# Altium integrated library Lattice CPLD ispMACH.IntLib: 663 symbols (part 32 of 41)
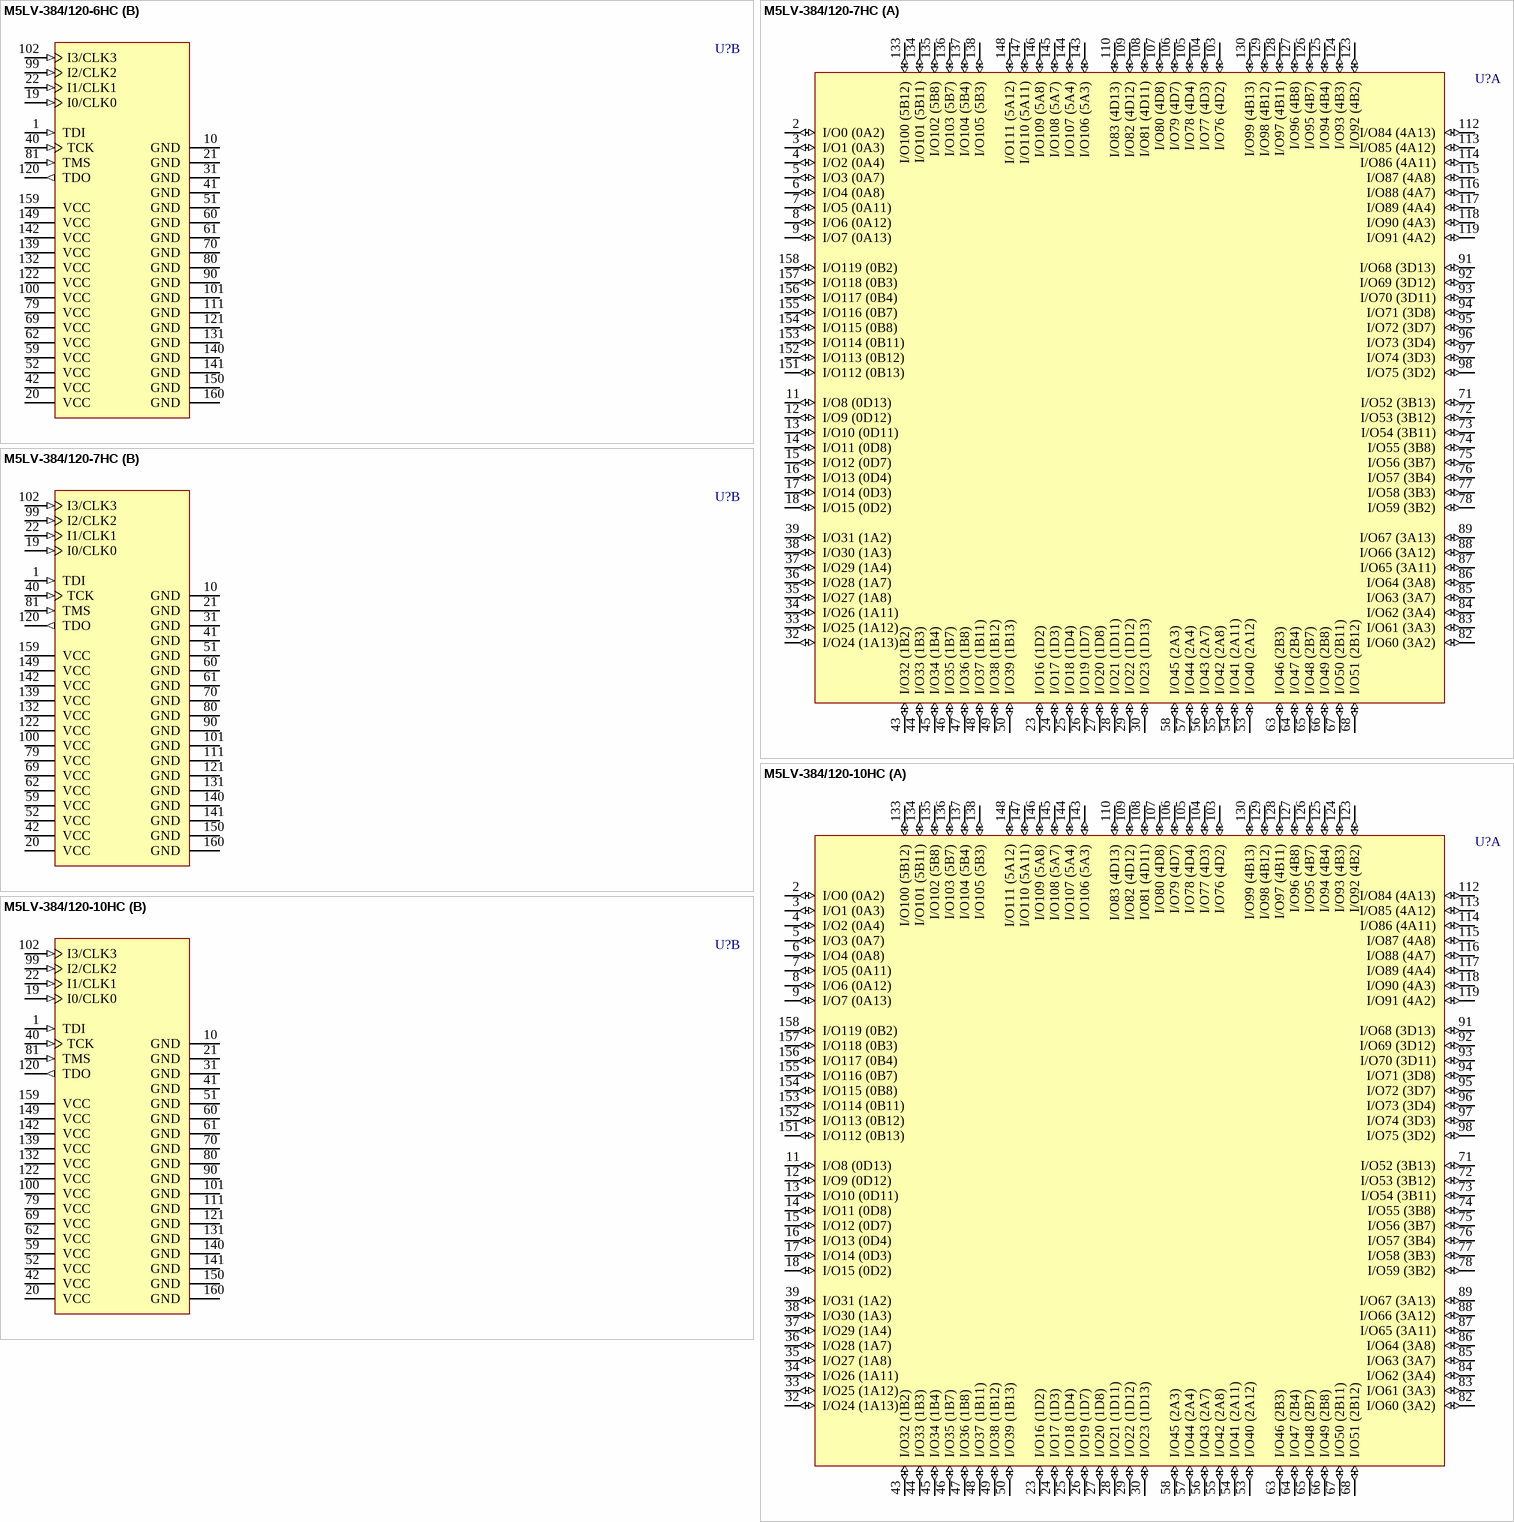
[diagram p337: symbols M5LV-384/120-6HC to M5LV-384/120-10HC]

## M5LV-384/120-7HC
designator U?
High-Density and High-I/O Complex PLD
footprint MQFP160_N (QFP, 160-Leads, Body 27.7 x 27.7mm, Pitch 0.65mm, IPC Medium Density)
footprint MQFP160_L (QFP, 160-Leads, Body 27.7 x 27.7mm, Pitch 0.65mm, IPC High Density)
footprint MQFP160_M (QFP, 160-Leads, Body 27.7 x 27.7mm, Pitch 0.65mm, IPC Low Density)
3D model M5LV-MQFP160 (160-Pin Quad Flat Pack 0.65 mm Pitch)
part A pins: 2 I/O0 (0A2) (io), 3 I/O1 (0A3) (io), 4 I/O2 (0A4) (io), 5 I/O3 (0A7) (io), 6 I/O4 (0A8) (io), 7 I/O5 (0A11) (io), 8 I/O6 (0A12) (io), 9 I/O7 (0A13) (io), 11 I/O8 (0D13) (io), 12 I/O9 (0D12) (io), 13 I/O10 (0D11) (io), 14 I/O11 (0D8) (io), 15 I/O12 (0D7) (io), 16 I/O13 (0D4) (io), 17 I/O14 (0D3) (io), 18 I/O15 (0D2) (io), 23 I/O16 (1D2) (io), 24 I/O17 (1D3) (io), 25 I/O18 (1D4) (io), 26 I/O19 (1D7) (io), 27 I/O20 (1D8) (io), 28 I/O21 (1D11) (io), 29 I/O22 (1D12) (io), 30 I/O23 (1D13) (io), 32 I/O24 (1A13) (io), 33 I/O25 (1A12) (io), 34 I/O26 (1A11) (io), 35 I/O27 (1A8) (io), 36 I/O28 (1A7) (io), 37 I/O29 (1A4) (io), 38 I/O30 (1A3) (io), 39 I/O31 (1A2) (io), 43 I/O32 (1B2) (io), 44 I/O33 (1B3) (io), 45 I/O34 (1B4) (io), 46 I/O35 (1B7) (io), 47 I/O36 (1B8) (io), 48 I/O37 (1B11) (io), 49 I/O38 (1B12) (io), 50 I/O39 (1B13) (io), 53 I/O40 (2A12) (io), 54 I/O41 (2A11) (io), 55 I/O42 (2A8) (io), 56 I/O43 (2A7) (io), 57 I/O44 (2A4) (io), 58 I/O45 (2A3) (io), 63 I/O46 (2B3) (io), 64 I/O47 (2B4) (io), 65 I/O48 (2B7) (io), 66 I/O49 (2B8) (io), 67 I/O50 (2B11) (io), 68 I/O51 (2B12) (io), 71 I/O52 (3B13) (io), 72 I/O53 (3B12) (io), 73 I/O54 (3B11) (io), 74 I/O55 (3B8) (io), 75 I/O56 (3B7) (io), 76 I/O57 (3B4) (io), 77 I/O58 (3B3) (io), 78 I/O59 (3B2) (io), 82 I/O60 (3A2) (io), 83 I/O61 (3A3) (io), 84 I/O62 (3A4) (io), 85 I/O63 (3A7) (io), 86 I/O64 (3A8) (io), 87 I/O65 (3A11) (io), 88 I/O66 (3A12) (io), 89 I/O67 (3A13) (io), 91 I/O68 (3D13) (io), 92 I/O69 (3D12) (io), 93 I/O70 (3D11) (io), 94 I/O71 (3D8) (io), 95 I/O72 (3D7) (io), 96 I/O73 (3D4) (io), 97 I/O74 (3D3) (io), 98 I/O75 (3D2) (io), 103 I/O76 (4D2) (io), 104 I/O77 (4D3) (io), 105 I/O78 (4D4) (io), 106 I/O79 (4D7) (io), 107 I/O80 (4D8) (io), 108 I/O81 (4D11) (io), 109 I/O82 (4D12) (io), 110 I/O83 (4D13) (io), 112 I/O84 (4A13) (io), 113 I/O85 (4A12) (io), 114 I/O86 (4A11) (io), 115 I/O87 (4A8) (io), 116 I/O88 (4A7) (io), 117 I/O89 (4A4) (io), 118 I/O90 (4A3) (io), 119 I/O91 (4A2) (io), 123 I/O92 (4B2) (io), 124 I/O93 (4B3) (io), 125 I/O94 (4B4) (io), 126 I/O95 (4B7) (io), 127 I/O96 (4B8) (io), 128 I/O97 (4B11) (io), 129 I/O98 (4B12) (io), 130 I/O99 (4B13) (io), 133 I/O100 (5B12) (io), 134 I/O101 (5B11) (io), 135 I/O102 (5B8) (io), 136 I/O103 (5B7) (io), 137 I/O104 (5B4) (io), 138 I/O105 (5B3) (io), 143 I/O106 (5A3) (io), 144 I/O107 (5A4) (io), 145 I/O108 (5A7) (io), 146 I/O109 (5A8) (io), 147 I/O110 (5A11) (io), 148 I/O111 (5A12) (io), 151 I/O112 (0B13) (io), 152 I/O113 (0B12) (io), 153 I/O114 (0B11) (io), 154 I/O115 (0B8) (io), 155 I/O116 (0B7) (io), 156 I/O117 (0B4) (io), 157 I/O118 (0B3) (io), 158 I/O119 (0B2) (io)
part B pins: 1 TDI (in), 10 GND (power), 19 I0/CLK0 (in), 20 VCC (power), 21 GND (power), 22 I1/CLK1 (in), 31 GND (power), 40 TCK (in), 41 GND (power), 42 VCC (power), 51 GND (power), 52 VCC (power), 59 VCC (power), 60 GND (power), 61 GND (power), 62 VCC (power), 69 VCC (power), 70 GND (power), 79 VCC (power), 80 GND (power), 81 TMS (in), 90 GND (power), 99 I2/CLK2 (in), 100 VCC (power), 101 GND (power), 102 I3/CLK3 (in), 111 GND (power), 120 TDO (out), 121 GND (power), 122 VCC (power), 131 GND (power), 132 VCC (power), 139 VCC (power), 140 GND (power), 141 GND (power), 142 VCC (power), 149 VCC (power), 150 GND (power), 159 VCC (power), 160 GND (power)

## M5LV-384/120-10HC
designator U?
High-Density and High-I/O Complex PLD
footprint MQFP160_N (QFP, 160-Leads, Body 27.7 x 27.7mm, Pitch 0.65mm, IPC Medium Density)
footprint MQFP160_L (QFP, 160-Leads, Body 27.7 x 27.7mm, Pitch 0.65mm, IPC High Density)
footprint MQFP160_M (QFP, 160-Leads, Body 27.7 x 27.7mm, Pitch 0.65mm, IPC Low Density)
3D model M5LV-MQFP160 (160-Pin Quad Flat Pack 0.65 mm Pitch)
part A pins: 2 I/O0 (0A2) (io), 3 I/O1 (0A3) (io), 4 I/O2 (0A4) (io), 5 I/O3 (0A7) (io), 6 I/O4 (0A8) (io), 7 I/O5 (0A11) (io), 8 I/O6 (0A12) (io), 9 I/O7 (0A13) (io), 11 I/O8 (0D13) (io), 12 I/O9 (0D12) (io), 13 I/O10 (0D11) (io), 14 I/O11 (0D8) (io), 15 I/O12 (0D7) (io), 16 I/O13 (0D4) (io), 17 I/O14 (0D3) (io), 18 I/O15 (0D2) (io), 23 I/O16 (1D2) (io), 24 I/O17 (1D3) (io), 25 I/O18 (1D4) (io), 26 I/O19 (1D7) (io), 27 I/O20 (1D8) (io), 28 I/O21 (1D11) (io), 29 I/O22 (1D12) (io), 30 I/O23 (1D13) (io), 32 I/O24 (1A13) (io), 33 I/O25 (1A12) (io), 34 I/O26 (1A11) (io), 35 I/O27 (1A8) (io), 36 I/O28 (1A7) (io), 37 I/O29 (1A4) (io), 38 I/O30 (1A3) (io), 39 I/O31 (1A2) (io), 43 I/O32 (1B2) (io), 44 I/O33 (1B3) (io), 45 I/O34 (1B4) (io), 46 I/O35 (1B7) (io), 47 I/O36 (1B8) (io), 48 I/O37 (1B11) (io), 49 I/O38 (1B12) (io), 50 I/O39 (1B13) (io), 53 I/O40 (2A12) (io), 54 I/O41 (2A11) (io), 55 I/O42 (2A8) (io), 56 I/O43 (2A7) (io), 57 I/O44 (2A4) (io), 58 I/O45 (2A3) (io), 63 I/O46 (2B3) (io), 64 I/O47 (2B4) (io), 65 I/O48 (2B7) (io), 66 I/O49 (2B8) (io), 67 I/O50 (2B11) (io), 68 I/O51 (2B12) (io), 71 I/O52 (3B13) (io), 72 I/O53 (3B12) (io), 73 I/O54 (3B11) (io), 74 I/O55 (3B8) (io), 75 I/O56 (3B7) (io), 76 I/O57 (3B4) (io), 77 I/O58 (3B3) (io), 78 I/O59 (3B2) (io), 82 I/O60 (3A2) (io), 83 I/O61 (3A3) (io), 84 I/O62 (3A4) (io), 85 I/O63 (3A7) (io), 86 I/O64 (3A8) (io), 87 I/O65 (3A11) (io), 88 I/O66 (3A12) (io), 89 I/O67 (3A13) (io), 91 I/O68 (3D13) (io), 92 I/O69 (3D12) (io), 93 I/O70 (3D11) (io), 94 I/O71 (3D8) (io), 95 I/O72 (3D7) (io), 96 I/O73 (3D4) (io), 97 I/O74 (3D3) (io), 98 I/O75 (3D2) (io), 103 I/O76 (4D2) (io), 104 I/O77 (4D3) (io), 105 I/O78 (4D4) (io), 106 I/O79 (4D7) (io), 107 I/O80 (4D8) (io), 108 I/O81 (4D11) (io), 109 I/O82 (4D12) (io), 110 I/O83 (4D13) (io), 112 I/O84 (4A13) (io), 113 I/O85 (4A12) (io), 114 I/O86 (4A11) (io), 115 I/O87 (4A8) (io), 116 I/O88 (4A7) (io), 117 I/O89 (4A4) (io), 118 I/O90 (4A3) (io), 119 I/O91 (4A2) (io), 123 I/O92 (4B2) (io), 124 I/O93 (4B3) (io), 125 I/O94 (4B4) (io), 126 I/O95 (4B7) (io), 127 I/O96 (4B8) (io), 128 I/O97 (4B11) (io), 129 I/O98 (4B12) (io), 130 I/O99 (4B13) (io), 133 I/O100 (5B12) (io), 134 I/O101 (5B11) (io), 135 I/O102 (5B8) (io), 136 I/O103 (5B7) (io), 137 I/O104 (5B4) (io), 138 I/O105 (5B3) (io), 143 I/O106 (5A3) (io), 144 I/O107 (5A4) (io), 145 I/O108 (5A7) (io), 146 I/O109 (5A8) (io), 147 I/O110 (5A11) (io), 148 I/O111 (5A12) (io), 151 I/O112 (0B13) (io), 152 I/O113 (0B12) (io), 153 I/O114 (0B11) (io), 154 I/O115 (0B8) (io), 155 I/O116 (0B7) (io), 156 I/O117 (0B4) (io), 157 I/O118 (0B3) (io), 158 I/O119 (0B2) (io)
part B pins: 1 TDI (in), 10 GND (power), 19 I0/CLK0 (in), 20 VCC (power), 21 GND (power), 22 I1/CLK1 (in), 31 GND (power), 40 TCK (in), 41 GND (power), 42 VCC (power), 51 GND (power), 52 VCC (power), 59 VCC (power), 60 GND (power), 61 GND (power), 62 VCC (power), 69 VCC (power), 70 GND (power), 79 VCC (power), 80 GND (power), 81 TMS (in), 90 GND (power), 99 I2/CLK2 (in), 100 VCC (power), 101 GND (power), 102 I3/CLK3 (in), 111 GND (power), 120 TDO (out), 121 GND (power), 122 VCC (power), 131 GND (power), 132 VCC (power), 139 VCC (power), 140 GND (power), 141 GND (power), 142 VCC (power), 149 VCC (power), 150 GND (power), 159 VCC (power), 160 GND (power)

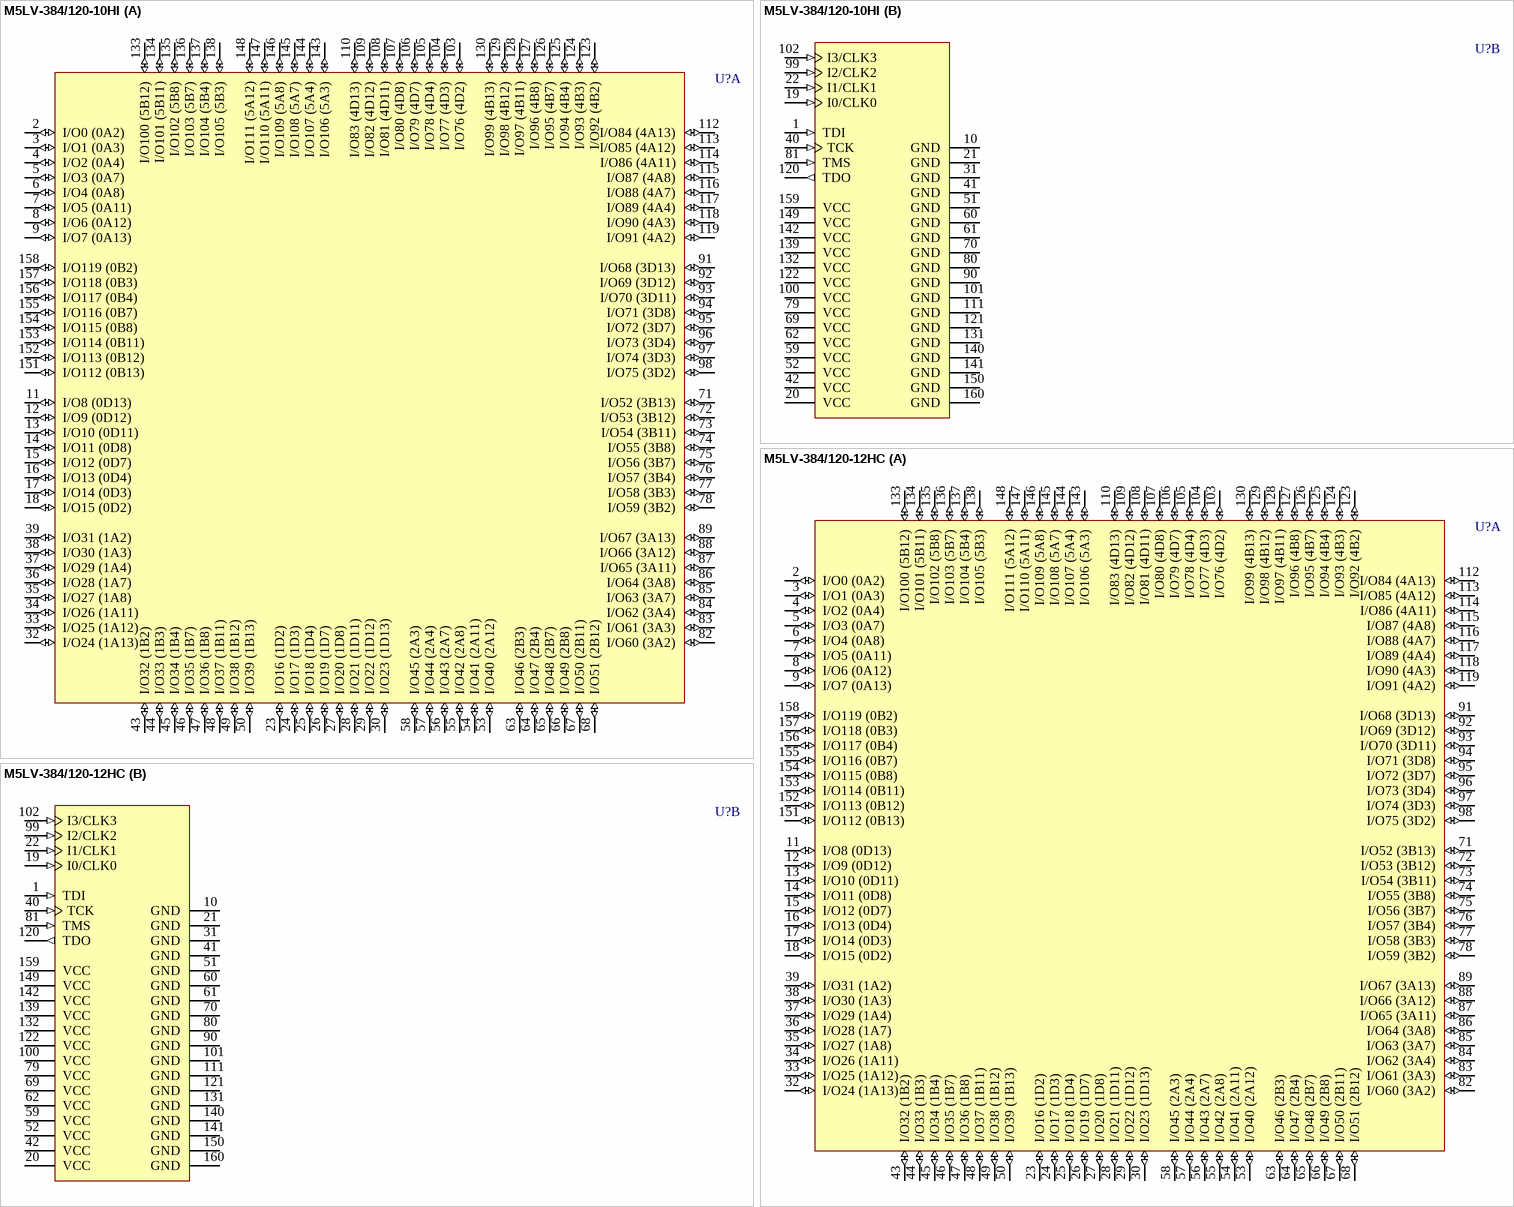
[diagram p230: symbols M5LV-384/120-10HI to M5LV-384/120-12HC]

## M5LV-384/120-10HI
designator U?
High-Density and High-I/O Complex PLD
footprint MQFP160_N (QFP, 160-Leads, Body 27.7 x 27.7mm, Pitch 0.65mm, IPC Medium Density)
footprint MQFP160_L (QFP, 160-Leads, Body 27.7 x 27.7mm, Pitch 0.65mm, IPC High Density)
footprint MQFP160_M (QFP, 160-Leads, Body 27.7 x 27.7mm, Pitch 0.65mm, IPC Low Density)
3D model M5LV-MQFP160 (160-Pin Quad Flat Pack 0.65 mm Pitch)
part A pins: 2 I/O0 (0A2) (io), 3 I/O1 (0A3) (io), 4 I/O2 (0A4) (io), 5 I/O3 (0A7) (io), 6 I/O4 (0A8) (io), 7 I/O5 (0A11) (io), 8 I/O6 (0A12) (io), 9 I/O7 (0A13) (io), 11 I/O8 (0D13) (io), 12 I/O9 (0D12) (io), 13 I/O10 (0D11) (io), 14 I/O11 (0D8) (io), 15 I/O12 (0D7) (io), 16 I/O13 (0D4) (io), 17 I/O14 (0D3) (io), 18 I/O15 (0D2) (io), 23 I/O16 (1D2) (io), 24 I/O17 (1D3) (io), 25 I/O18 (1D4) (io), 26 I/O19 (1D7) (io), 27 I/O20 (1D8) (io), 28 I/O21 (1D11) (io), 29 I/O22 (1D12) (io), 30 I/O23 (1D13) (io), 32 I/O24 (1A13) (io), 33 I/O25 (1A12) (io), 34 I/O26 (1A11) (io), 35 I/O27 (1A8) (io), 36 I/O28 (1A7) (io), 37 I/O29 (1A4) (io), 38 I/O30 (1A3) (io), 39 I/O31 (1A2) (io), 43 I/O32 (1B2) (io), 44 I/O33 (1B3) (io), 45 I/O34 (1B4) (io), 46 I/O35 (1B7) (io), 47 I/O36 (1B8) (io), 48 I/O37 (1B11) (io), 49 I/O38 (1B12) (io), 50 I/O39 (1B13) (io), 53 I/O40 (2A12) (io), 54 I/O41 (2A11) (io), 55 I/O42 (2A8) (io), 56 I/O43 (2A7) (io), 57 I/O44 (2A4) (io), 58 I/O45 (2A3) (io), 63 I/O46 (2B3) (io), 64 I/O47 (2B4) (io), 65 I/O48 (2B7) (io), 66 I/O49 (2B8) (io), 67 I/O50 (2B11) (io), 68 I/O51 (2B12) (io), 71 I/O52 (3B13) (io), 72 I/O53 (3B12) (io), 73 I/O54 (3B11) (io), 74 I/O55 (3B8) (io), 75 I/O56 (3B7) (io), 76 I/O57 (3B4) (io), 77 I/O58 (3B3) (io), 78 I/O59 (3B2) (io), 82 I/O60 (3A2) (io), 83 I/O61 (3A3) (io), 84 I/O62 (3A4) (io), 85 I/O63 (3A7) (io), 86 I/O64 (3A8) (io), 87 I/O65 (3A11) (io), 88 I/O66 (3A12) (io), 89 I/O67 (3A13) (io), 91 I/O68 (3D13) (io), 92 I/O69 (3D12) (io), 93 I/O70 (3D11) (io), 94 I/O71 (3D8) (io), 95 I/O72 (3D7) (io), 96 I/O73 (3D4) (io), 97 I/O74 (3D3) (io), 98 I/O75 (3D2) (io), 103 I/O76 (4D2) (io), 104 I/O77 (4D3) (io), 105 I/O78 (4D4) (io), 106 I/O79 (4D7) (io), 107 I/O80 (4D8) (io), 108 I/O81 (4D11) (io), 109 I/O82 (4D12) (io), 110 I/O83 (4D13) (io), 112 I/O84 (4A13) (io), 113 I/O85 (4A12) (io), 114 I/O86 (4A11) (io), 115 I/O87 (4A8) (io), 116 I/O88 (4A7) (io), 117 I/O89 (4A4) (io), 118 I/O90 (4A3) (io), 119 I/O91 (4A2) (io), 123 I/O92 (4B2) (io), 124 I/O93 (4B3) (io), 125 I/O94 (4B4) (io), 126 I/O95 (4B7) (io), 127 I/O96 (4B8) (io), 128 I/O97 (4B11) (io), 129 I/O98 (4B12) (io), 130 I/O99 (4B13) (io), 133 I/O100 (5B12) (io), 134 I/O101 (5B11) (io), 135 I/O102 (5B8) (io), 136 I/O103 (5B7) (io), 137 I/O104 (5B4) (io), 138 I/O105 (5B3) (io), 143 I/O106 (5A3) (io), 144 I/O107 (5A4) (io), 145 I/O108 (5A7) (io), 146 I/O109 (5A8) (io), 147 I/O110 (5A11) (io), 148 I/O111 (5A12) (io), 151 I/O112 (0B13) (io), 152 I/O113 (0B12) (io), 153 I/O114 (0B11) (io), 154 I/O115 (0B8) (io), 155 I/O116 (0B7) (io), 156 I/O117 (0B4) (io), 157 I/O118 (0B3) (io), 158 I/O119 (0B2) (io)
part B pins: 1 TDI (in), 10 GND (power), 19 I0/CLK0 (in), 20 VCC (power), 21 GND (power), 22 I1/CLK1 (in), 31 GND (power), 40 TCK (in), 41 GND (power), 42 VCC (power), 51 GND (power), 52 VCC (power), 59 VCC (power), 60 GND (power), 61 GND (power), 62 VCC (power), 69 VCC (power), 70 GND (power), 79 VCC (power), 80 GND (power), 81 TMS (in), 90 GND (power), 99 I2/CLK2 (in), 100 VCC (power), 101 GND (power), 102 I3/CLK3 (in), 111 GND (power), 120 TDO (out), 121 GND (power), 122 VCC (power), 131 GND (power), 132 VCC (power), 139 VCC (power), 140 GND (power), 141 GND (power), 142 VCC (power), 149 VCC (power), 150 GND (power), 159 VCC (power), 160 GND (power)

## M5LV-384/120-12HC
designator U?
High-Density and High-I/O Complex PLD
footprint MQFP160_N (QFP, 160-Leads, Body 27.7 x 27.7mm, Pitch 0.65mm, IPC Medium Density)
footprint MQFP160_L (QFP, 160-Leads, Body 27.7 x 27.7mm, Pitch 0.65mm, IPC High Density)
footprint MQFP160_M (QFP, 160-Leads, Body 27.7 x 27.7mm, Pitch 0.65mm, IPC Low Density)
3D model M5LV-MQFP160 (160-Pin Quad Flat Pack 0.65 mm Pitch)
part A pins: 2 I/O0 (0A2) (io), 3 I/O1 (0A3) (io), 4 I/O2 (0A4) (io), 5 I/O3 (0A7) (io), 6 I/O4 (0A8) (io), 7 I/O5 (0A11) (io), 8 I/O6 (0A12) (io), 9 I/O7 (0A13) (io), 11 I/O8 (0D13) (io), 12 I/O9 (0D12) (io), 13 I/O10 (0D11) (io), 14 I/O11 (0D8) (io), 15 I/O12 (0D7) (io), 16 I/O13 (0D4) (io), 17 I/O14 (0D3) (io), 18 I/O15 (0D2) (io), 23 I/O16 (1D2) (io), 24 I/O17 (1D3) (io), 25 I/O18 (1D4) (io), 26 I/O19 (1D7) (io), 27 I/O20 (1D8) (io), 28 I/O21 (1D11) (io), 29 I/O22 (1D12) (io), 30 I/O23 (1D13) (io), 32 I/O24 (1A13) (io), 33 I/O25 (1A12) (io), 34 I/O26 (1A11) (io), 35 I/O27 (1A8) (io), 36 I/O28 (1A7) (io), 37 I/O29 (1A4) (io), 38 I/O30 (1A3) (io), 39 I/O31 (1A2) (io), 43 I/O32 (1B2) (io), 44 I/O33 (1B3) (io), 45 I/O34 (1B4) (io), 46 I/O35 (1B7) (io), 47 I/O36 (1B8) (io), 48 I/O37 (1B11) (io), 49 I/O38 (1B12) (io), 50 I/O39 (1B13) (io), 53 I/O40 (2A12) (io), 54 I/O41 (2A11) (io), 55 I/O42 (2A8) (io), 56 I/O43 (2A7) (io), 57 I/O44 (2A4) (io), 58 I/O45 (2A3) (io), 63 I/O46 (2B3) (io), 64 I/O47 (2B4) (io), 65 I/O48 (2B7) (io), 66 I/O49 (2B8) (io), 67 I/O50 (2B11) (io), 68 I/O51 (2B12) (io), 71 I/O52 (3B13) (io), 72 I/O53 (3B12) (io), 73 I/O54 (3B11) (io), 74 I/O55 (3B8) (io), 75 I/O56 (3B7) (io), 76 I/O57 (3B4) (io), 77 I/O58 (3B3) (io), 78 I/O59 (3B2) (io), 82 I/O60 (3A2) (io), 83 I/O61 (3A3) (io), 84 I/O62 (3A4) (io), 85 I/O63 (3A7) (io), 86 I/O64 (3A8) (io), 87 I/O65 (3A11) (io), 88 I/O66 (3A12) (io), 89 I/O67 (3A13) (io), 91 I/O68 (3D13) (io), 92 I/O69 (3D12) (io), 93 I/O70 (3D11) (io), 94 I/O71 (3D8) (io), 95 I/O72 (3D7) (io), 96 I/O73 (3D4) (io), 97 I/O74 (3D3) (io), 98 I/O75 (3D2) (io), 103 I/O76 (4D2) (io), 104 I/O77 (4D3) (io), 105 I/O78 (4D4) (io), 106 I/O79 (4D7) (io), 107 I/O80 (4D8) (io), 108 I/O81 (4D11) (io), 109 I/O82 (4D12) (io), 110 I/O83 (4D13) (io), 112 I/O84 (4A13) (io), 113 I/O85 (4A12) (io), 114 I/O86 (4A11) (io), 115 I/O87 (4A8) (io), 116 I/O88 (4A7) (io), 117 I/O89 (4A4) (io), 118 I/O90 (4A3) (io), 119 I/O91 (4A2) (io), 123 I/O92 (4B2) (io), 124 I/O93 (4B3) (io), 125 I/O94 (4B4) (io), 126 I/O95 (4B7) (io), 127 I/O96 (4B8) (io), 128 I/O97 (4B11) (io), 129 I/O98 (4B12) (io), 130 I/O99 (4B13) (io), 133 I/O100 (5B12) (io), 134 I/O101 (5B11) (io), 135 I/O102 (5B8) (io), 136 I/O103 (5B7) (io), 137 I/O104 (5B4) (io), 138 I/O105 (5B3) (io), 143 I/O106 (5A3) (io), 144 I/O107 (5A4) (io), 145 I/O108 (5A7) (io), 146 I/O109 (5A8) (io), 147 I/O110 (5A11) (io), 148 I/O111 (5A12) (io), 151 I/O112 (0B13) (io), 152 I/O113 (0B12) (io), 153 I/O114 (0B11) (io), 154 I/O115 (0B8) (io), 155 I/O116 (0B7) (io), 156 I/O117 (0B4) (io), 157 I/O118 (0B3) (io), 158 I/O119 (0B2) (io)
part B pins: 1 TDI (in), 10 GND (power), 19 I0/CLK0 (in), 20 VCC (power), 21 GND (power), 22 I1/CLK1 (in), 31 GND (power), 40 TCK (in), 41 GND (power), 42 VCC (power), 51 GND (power), 52 VCC (power), 59 VCC (power), 60 GND (power), 61 GND (power), 62 VCC (power), 69 VCC (power), 70 GND (power), 79 VCC (power), 80 GND (power), 81 TMS (in), 90 GND (power), 99 I2/CLK2 (in), 100 VCC (power), 101 GND (power), 102 I3/CLK3 (in), 111 GND (power), 120 TDO (out), 121 GND (power), 122 VCC (power), 131 GND (power), 132 VCC (power), 139 VCC (power), 140 GND (power), 141 GND (power), 142 VCC (power), 149 VCC (power), 150 GND (power), 159 VCC (power), 160 GND (power)

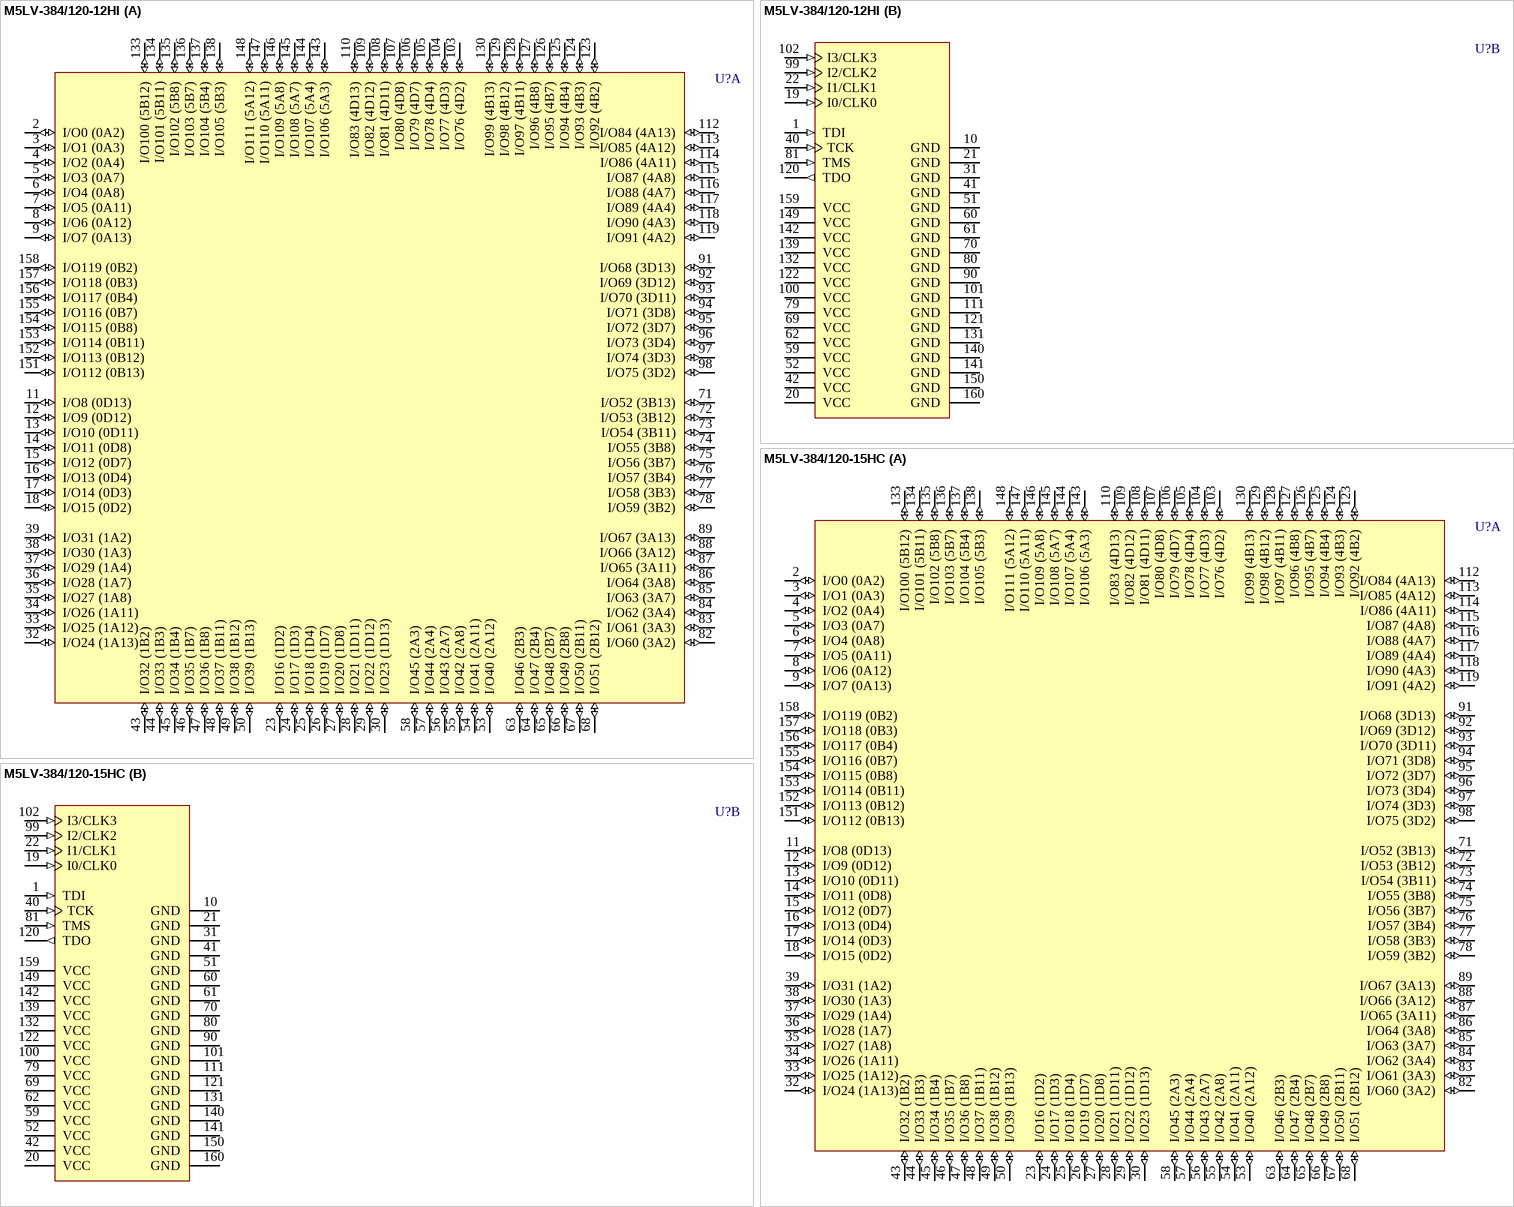
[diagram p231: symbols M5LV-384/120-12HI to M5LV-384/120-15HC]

## M5LV-384/120-12HI
designator U?
High-Density and High-I/O Complex PLD
footprint MQFP160_N (QFP, 160-Leads, Body 27.7 x 27.7mm, Pitch 0.65mm, IPC Medium Density)
footprint MQFP160_L (QFP, 160-Leads, Body 27.7 x 27.7mm, Pitch 0.65mm, IPC High Density)
footprint MQFP160_M (QFP, 160-Leads, Body 27.7 x 27.7mm, Pitch 0.65mm, IPC Low Density)
3D model M5LV-MQFP160 (160-Pin Quad Flat Pack 0.65 mm Pitch)
part A pins: 2 I/O0 (0A2) (io), 3 I/O1 (0A3) (io), 4 I/O2 (0A4) (io), 5 I/O3 (0A7) (io), 6 I/O4 (0A8) (io), 7 I/O5 (0A11) (io), 8 I/O6 (0A12) (io), 9 I/O7 (0A13) (io), 11 I/O8 (0D13) (io), 12 I/O9 (0D12) (io), 13 I/O10 (0D11) (io), 14 I/O11 (0D8) (io), 15 I/O12 (0D7) (io), 16 I/O13 (0D4) (io), 17 I/O14 (0D3) (io), 18 I/O15 (0D2) (io), 23 I/O16 (1D2) (io), 24 I/O17 (1D3) (io), 25 I/O18 (1D4) (io), 26 I/O19 (1D7) (io), 27 I/O20 (1D8) (io), 28 I/O21 (1D11) (io), 29 I/O22 (1D12) (io), 30 I/O23 (1D13) (io), 32 I/O24 (1A13) (io), 33 I/O25 (1A12) (io), 34 I/O26 (1A11) (io), 35 I/O27 (1A8) (io), 36 I/O28 (1A7) (io), 37 I/O29 (1A4) (io), 38 I/O30 (1A3) (io), 39 I/O31 (1A2) (io), 43 I/O32 (1B2) (io), 44 I/O33 (1B3) (io), 45 I/O34 (1B4) (io), 46 I/O35 (1B7) (io), 47 I/O36 (1B8) (io), 48 I/O37 (1B11) (io), 49 I/O38 (1B12) (io), 50 I/O39 (1B13) (io), 53 I/O40 (2A12) (io), 54 I/O41 (2A11) (io), 55 I/O42 (2A8) (io), 56 I/O43 (2A7) (io), 57 I/O44 (2A4) (io), 58 I/O45 (2A3) (io), 63 I/O46 (2B3) (io), 64 I/O47 (2B4) (io), 65 I/O48 (2B7) (io), 66 I/O49 (2B8) (io), 67 I/O50 (2B11) (io), 68 I/O51 (2B12) (io), 71 I/O52 (3B13) (io), 72 I/O53 (3B12) (io), 73 I/O54 (3B11) (io), 74 I/O55 (3B8) (io), 75 I/O56 (3B7) (io), 76 I/O57 (3B4) (io), 77 I/O58 (3B3) (io), 78 I/O59 (3B2) (io), 82 I/O60 (3A2) (io), 83 I/O61 (3A3) (io), 84 I/O62 (3A4) (io), 85 I/O63 (3A7) (io), 86 I/O64 (3A8) (io), 87 I/O65 (3A11) (io), 88 I/O66 (3A12) (io), 89 I/O67 (3A13) (io), 91 I/O68 (3D13) (io), 92 I/O69 (3D12) (io), 93 I/O70 (3D11) (io), 94 I/O71 (3D8) (io), 95 I/O72 (3D7) (io), 96 I/O73 (3D4) (io), 97 I/O74 (3D3) (io), 98 I/O75 (3D2) (io), 103 I/O76 (4D2) (io), 104 I/O77 (4D3) (io), 105 I/O78 (4D4) (io), 106 I/O79 (4D7) (io), 107 I/O80 (4D8) (io), 108 I/O81 (4D11) (io), 109 I/O82 (4D12) (io), 110 I/O83 (4D13) (io), 112 I/O84 (4A13) (io), 113 I/O85 (4A12) (io), 114 I/O86 (4A11) (io), 115 I/O87 (4A8) (io), 116 I/O88 (4A7) (io), 117 I/O89 (4A4) (io), 118 I/O90 (4A3) (io), 119 I/O91 (4A2) (io), 123 I/O92 (4B2) (io), 124 I/O93 (4B3) (io), 125 I/O94 (4B4) (io), 126 I/O95 (4B7) (io), 127 I/O96 (4B8) (io), 128 I/O97 (4B11) (io), 129 I/O98 (4B12) (io), 130 I/O99 (4B13) (io), 133 I/O100 (5B12) (io), 134 I/O101 (5B11) (io), 135 I/O102 (5B8) (io), 136 I/O103 (5B7) (io), 137 I/O104 (5B4) (io), 138 I/O105 (5B3) (io), 143 I/O106 (5A3) (io), 144 I/O107 (5A4) (io), 145 I/O108 (5A7) (io), 146 I/O109 (5A8) (io), 147 I/O110 (5A11) (io), 148 I/O111 (5A12) (io), 151 I/O112 (0B13) (io), 152 I/O113 (0B12) (io), 153 I/O114 (0B11) (io), 154 I/O115 (0B8) (io), 155 I/O116 (0B7) (io), 156 I/O117 (0B4) (io), 157 I/O118 (0B3) (io), 158 I/O119 (0B2) (io)
part B pins: 1 TDI (in), 10 GND (power), 19 I0/CLK0 (in), 20 VCC (power), 21 GND (power), 22 I1/CLK1 (in), 31 GND (power), 40 TCK (in), 41 GND (power), 42 VCC (power), 51 GND (power), 52 VCC (power), 59 VCC (power), 60 GND (power), 61 GND (power), 62 VCC (power), 69 VCC (power), 70 GND (power), 79 VCC (power), 80 GND (power), 81 TMS (in), 90 GND (power), 99 I2/CLK2 (in), 100 VCC (power), 101 GND (power), 102 I3/CLK3 (in), 111 GND (power), 120 TDO (out), 121 GND (power), 122 VCC (power), 131 GND (power), 132 VCC (power), 139 VCC (power), 140 GND (power), 141 GND (power), 142 VCC (power), 149 VCC (power), 150 GND (power), 159 VCC (power), 160 GND (power)

## M5LV-384/120-15HC
designator U?
High-Density and High-I/O Complex PLD
footprint MQFP160_N (QFP, 160-Leads, Body 27.7 x 27.7mm, Pitch 0.65mm, IPC Medium Density)
footprint MQFP160_L (QFP, 160-Leads, Body 27.7 x 27.7mm, Pitch 0.65mm, IPC High Density)
footprint MQFP160_M (QFP, 160-Leads, Body 27.7 x 27.7mm, Pitch 0.65mm, IPC Low Density)
3D model M5LV-MQFP160 (160-Pin Quad Flat Pack 0.65 mm Pitch)
part A pins: 2 I/O0 (0A2) (io), 3 I/O1 (0A3) (io), 4 I/O2 (0A4) (io), 5 I/O3 (0A7) (io), 6 I/O4 (0A8) (io), 7 I/O5 (0A11) (io), 8 I/O6 (0A12) (io), 9 I/O7 (0A13) (io), 11 I/O8 (0D13) (io), 12 I/O9 (0D12) (io), 13 I/O10 (0D11) (io), 14 I/O11 (0D8) (io), 15 I/O12 (0D7) (io), 16 I/O13 (0D4) (io), 17 I/O14 (0D3) (io), 18 I/O15 (0D2) (io), 23 I/O16 (1D2) (io), 24 I/O17 (1D3) (io), 25 I/O18 (1D4) (io), 26 I/O19 (1D7) (io), 27 I/O20 (1D8) (io), 28 I/O21 (1D11) (io), 29 I/O22 (1D12) (io), 30 I/O23 (1D13) (io), 32 I/O24 (1A13) (io), 33 I/O25 (1A12) (io), 34 I/O26 (1A11) (io), 35 I/O27 (1A8) (io), 36 I/O28 (1A7) (io), 37 I/O29 (1A4) (io), 38 I/O30 (1A3) (io), 39 I/O31 (1A2) (io), 43 I/O32 (1B2) (io), 44 I/O33 (1B3) (io), 45 I/O34 (1B4) (io), 46 I/O35 (1B7) (io), 47 I/O36 (1B8) (io), 48 I/O37 (1B11) (io), 49 I/O38 (1B12) (io), 50 I/O39 (1B13) (io), 53 I/O40 (2A12) (io), 54 I/O41 (2A11) (io), 55 I/O42 (2A8) (io), 56 I/O43 (2A7) (io), 57 I/O44 (2A4) (io), 58 I/O45 (2A3) (io), 63 I/O46 (2B3) (io), 64 I/O47 (2B4) (io), 65 I/O48 (2B7) (io), 66 I/O49 (2B8) (io), 67 I/O50 (2B11) (io), 68 I/O51 (2B12) (io), 71 I/O52 (3B13) (io), 72 I/O53 (3B12) (io), 73 I/O54 (3B11) (io), 74 I/O55 (3B8) (io), 75 I/O56 (3B7) (io), 76 I/O57 (3B4) (io), 77 I/O58 (3B3) (io), 78 I/O59 (3B2) (io), 82 I/O60 (3A2) (io), 83 I/O61 (3A3) (io), 84 I/O62 (3A4) (io), 85 I/O63 (3A7) (io), 86 I/O64 (3A8) (io), 87 I/O65 (3A11) (io), 88 I/O66 (3A12) (io), 89 I/O67 (3A13) (io), 91 I/O68 (3D13) (io), 92 I/O69 (3D12) (io), 93 I/O70 (3D11) (io), 94 I/O71 (3D8) (io), 95 I/O72 (3D7) (io), 96 I/O73 (3D4) (io), 97 I/O74 (3D3) (io), 98 I/O75 (3D2) (io), 103 I/O76 (4D2) (io), 104 I/O77 (4D3) (io), 105 I/O78 (4D4) (io), 106 I/O79 (4D7) (io), 107 I/O80 (4D8) (io), 108 I/O81 (4D11) (io), 109 I/O82 (4D12) (io), 110 I/O83 (4D13) (io), 112 I/O84 (4A13) (io), 113 I/O85 (4A12) (io), 114 I/O86 (4A11) (io), 115 I/O87 (4A8) (io), 116 I/O88 (4A7) (io), 117 I/O89 (4A4) (io), 118 I/O90 (4A3) (io), 119 I/O91 (4A2) (io), 123 I/O92 (4B2) (io), 124 I/O93 (4B3) (io), 125 I/O94 (4B4) (io), 126 I/O95 (4B7) (io), 127 I/O96 (4B8) (io), 128 I/O97 (4B11) (io), 129 I/O98 (4B12) (io), 130 I/O99 (4B13) (io), 133 I/O100 (5B12) (io), 134 I/O101 (5B11) (io), 135 I/O102 (5B8) (io), 136 I/O103 (5B7) (io), 137 I/O104 (5B4) (io), 138 I/O105 (5B3) (io), 143 I/O106 (5A3) (io), 144 I/O107 (5A4) (io), 145 I/O108 (5A7) (io), 146 I/O109 (5A8) (io), 147 I/O110 (5A11) (io), 148 I/O111 (5A12) (io), 151 I/O112 (0B13) (io), 152 I/O113 (0B12) (io), 153 I/O114 (0B11) (io), 154 I/O115 (0B8) (io), 155 I/O116 (0B7) (io), 156 I/O117 (0B4) (io), 157 I/O118 (0B3) (io), 158 I/O119 (0B2) (io)
part B pins: 1 TDI (in), 10 GND (power), 19 I0/CLK0 (in), 20 VCC (power), 21 GND (power), 22 I1/CLK1 (in), 31 GND (power), 40 TCK (in), 41 GND (power), 42 VCC (power), 51 GND (power), 52 VCC (power), 59 VCC (power), 60 GND (power), 61 GND (power), 62 VCC (power), 69 VCC (power), 70 GND (power), 79 VCC (power), 80 GND (power), 81 TMS (in), 90 GND (power), 99 I2/CLK2 (in), 100 VCC (power), 101 GND (power), 102 I3/CLK3 (in), 111 GND (power), 120 TDO (out), 121 GND (power), 122 VCC (power), 131 GND (power), 132 VCC (power), 139 VCC (power), 140 GND (power), 141 GND (power), 142 VCC (power), 149 VCC (power), 150 GND (power), 159 VCC (power), 160 GND (power)

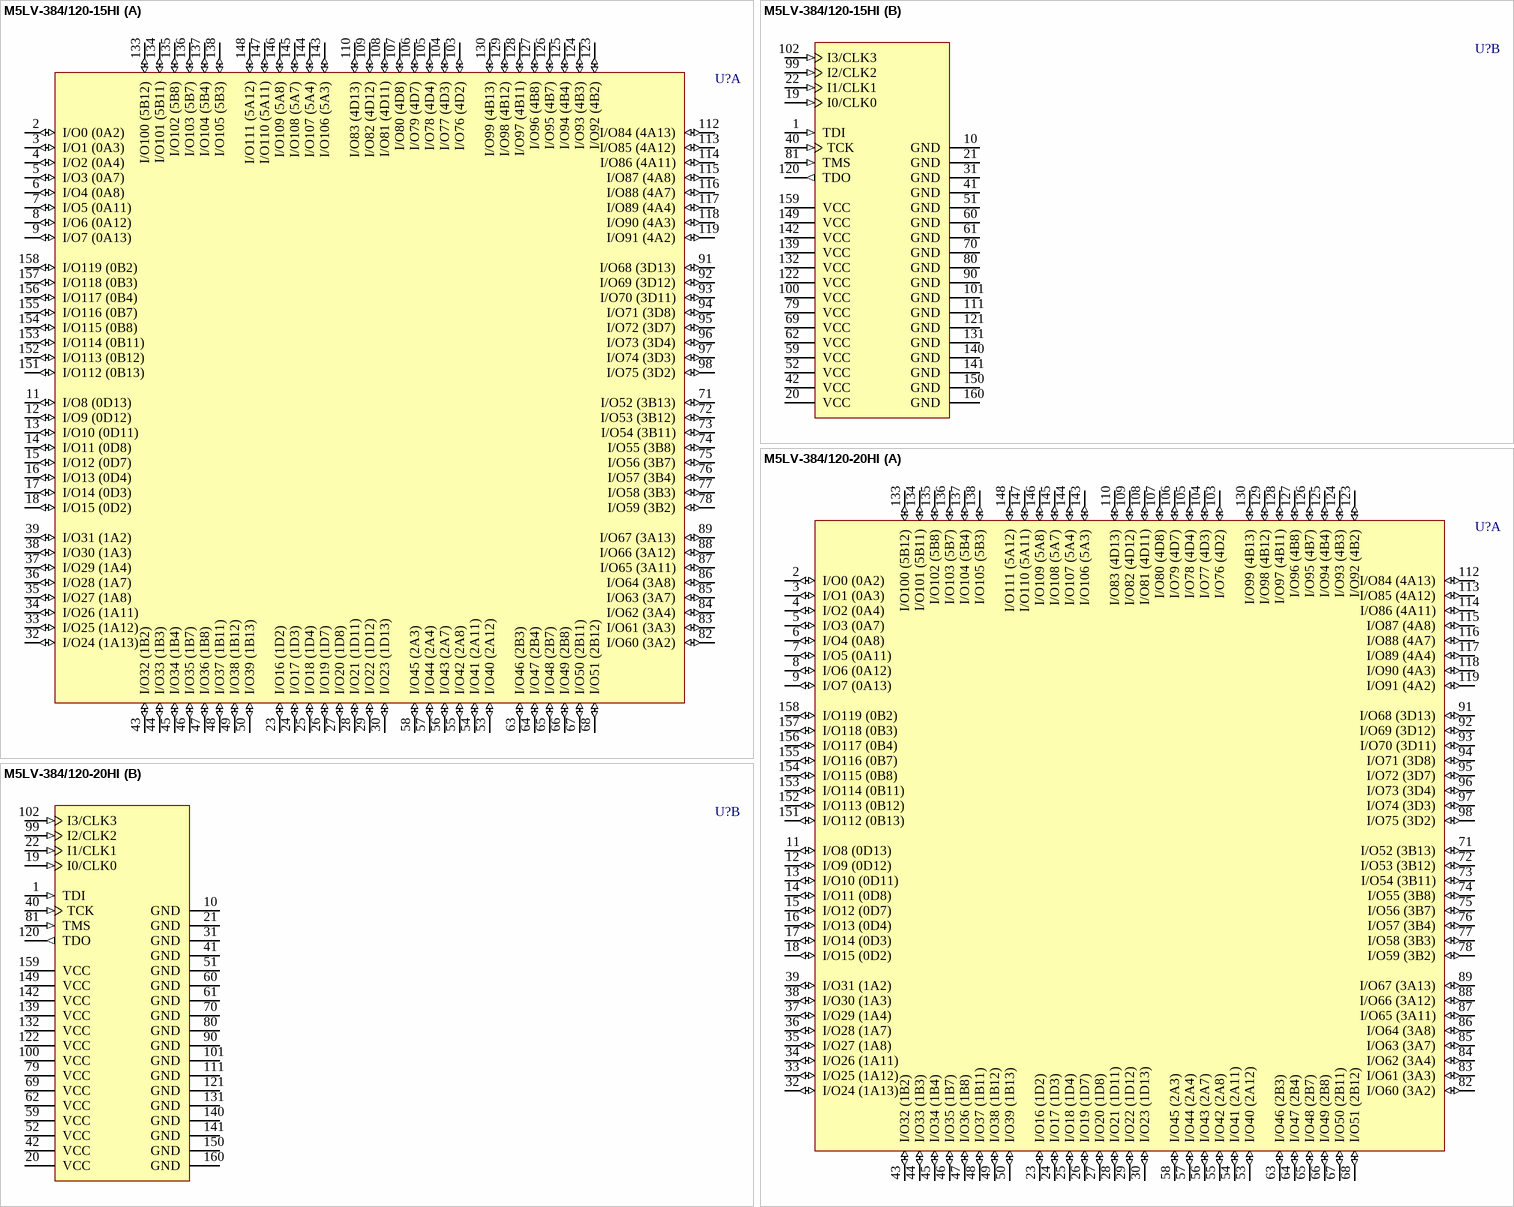
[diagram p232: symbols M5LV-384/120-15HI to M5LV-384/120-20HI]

## M5LV-384/120-15HI
designator U?
High-Density and High-I/O Complex PLD
footprint MQFP160_N (QFP, 160-Leads, Body 27.7 x 27.7mm, Pitch 0.65mm, IPC Medium Density)
footprint MQFP160_L (QFP, 160-Leads, Body 27.7 x 27.7mm, Pitch 0.65mm, IPC High Density)
footprint MQFP160_M (QFP, 160-Leads, Body 27.7 x 27.7mm, Pitch 0.65mm, IPC Low Density)
3D model M5LV-MQFP160 (160-Pin Quad Flat Pack 0.65 mm Pitch)
part A pins: 2 I/O0 (0A2) (io), 3 I/O1 (0A3) (io), 4 I/O2 (0A4) (io), 5 I/O3 (0A7) (io), 6 I/O4 (0A8) (io), 7 I/O5 (0A11) (io), 8 I/O6 (0A12) (io), 9 I/O7 (0A13) (io), 11 I/O8 (0D13) (io), 12 I/O9 (0D12) (io), 13 I/O10 (0D11) (io), 14 I/O11 (0D8) (io), 15 I/O12 (0D7) (io), 16 I/O13 (0D4) (io), 17 I/O14 (0D3) (io), 18 I/O15 (0D2) (io), 23 I/O16 (1D2) (io), 24 I/O17 (1D3) (io), 25 I/O18 (1D4) (io), 26 I/O19 (1D7) (io), 27 I/O20 (1D8) (io), 28 I/O21 (1D11) (io), 29 I/O22 (1D12) (io), 30 I/O23 (1D13) (io), 32 I/O24 (1A13) (io), 33 I/O25 (1A12) (io), 34 I/O26 (1A11) (io), 35 I/O27 (1A8) (io), 36 I/O28 (1A7) (io), 37 I/O29 (1A4) (io), 38 I/O30 (1A3) (io), 39 I/O31 (1A2) (io), 43 I/O32 (1B2) (io), 44 I/O33 (1B3) (io), 45 I/O34 (1B4) (io), 46 I/O35 (1B7) (io), 47 I/O36 (1B8) (io), 48 I/O37 (1B11) (io), 49 I/O38 (1B12) (io), 50 I/O39 (1B13) (io), 53 I/O40 (2A12) (io), 54 I/O41 (2A11) (io), 55 I/O42 (2A8) (io), 56 I/O43 (2A7) (io), 57 I/O44 (2A4) (io), 58 I/O45 (2A3) (io), 63 I/O46 (2B3) (io), 64 I/O47 (2B4) (io), 65 I/O48 (2B7) (io), 66 I/O49 (2B8) (io), 67 I/O50 (2B11) (io), 68 I/O51 (2B12) (io), 71 I/O52 (3B13) (io), 72 I/O53 (3B12) (io), 73 I/O54 (3B11) (io), 74 I/O55 (3B8) (io), 75 I/O56 (3B7) (io), 76 I/O57 (3B4) (io), 77 I/O58 (3B3) (io), 78 I/O59 (3B2) (io), 82 I/O60 (3A2) (io), 83 I/O61 (3A3) (io), 84 I/O62 (3A4) (io), 85 I/O63 (3A7) (io), 86 I/O64 (3A8) (io), 87 I/O65 (3A11) (io), 88 I/O66 (3A12) (io), 89 I/O67 (3A13) (io), 91 I/O68 (3D13) (io), 92 I/O69 (3D12) (io), 93 I/O70 (3D11) (io), 94 I/O71 (3D8) (io), 95 I/O72 (3D7) (io), 96 I/O73 (3D4) (io), 97 I/O74 (3D3) (io), 98 I/O75 (3D2) (io), 103 I/O76 (4D2) (io), 104 I/O77 (4D3) (io), 105 I/O78 (4D4) (io), 106 I/O79 (4D7) (io), 107 I/O80 (4D8) (io), 108 I/O81 (4D11) (io), 109 I/O82 (4D12) (io), 110 I/O83 (4D13) (io), 112 I/O84 (4A13) (io), 113 I/O85 (4A12) (io), 114 I/O86 (4A11) (io), 115 I/O87 (4A8) (io), 116 I/O88 (4A7) (io), 117 I/O89 (4A4) (io), 118 I/O90 (4A3) (io), 119 I/O91 (4A2) (io), 123 I/O92 (4B2) (io), 124 I/O93 (4B3) (io), 125 I/O94 (4B4) (io), 126 I/O95 (4B7) (io), 127 I/O96 (4B8) (io), 128 I/O97 (4B11) (io), 129 I/O98 (4B12) (io), 130 I/O99 (4B13) (io), 133 I/O100 (5B12) (io), 134 I/O101 (5B11) (io), 135 I/O102 (5B8) (io), 136 I/O103 (5B7) (io), 137 I/O104 (5B4) (io), 138 I/O105 (5B3) (io), 143 I/O106 (5A3) (io), 144 I/O107 (5A4) (io), 145 I/O108 (5A7) (io), 146 I/O109 (5A8) (io), 147 I/O110 (5A11) (io), 148 I/O111 (5A12) (io), 151 I/O112 (0B13) (io), 152 I/O113 (0B12) (io), 153 I/O114 (0B11) (io), 154 I/O115 (0B8) (io), 155 I/O116 (0B7) (io), 156 I/O117 (0B4) (io), 157 I/O118 (0B3) (io), 158 I/O119 (0B2) (io)
part B pins: 1 TDI (in), 10 GND (power), 19 I0/CLK0 (in), 20 VCC (power), 21 GND (power), 22 I1/CLK1 (in), 31 GND (power), 40 TCK (in), 41 GND (power), 42 VCC (power), 51 GND (power), 52 VCC (power), 59 VCC (power), 60 GND (power), 61 GND (power), 62 VCC (power), 69 VCC (power), 70 GND (power), 79 VCC (power), 80 GND (power), 81 TMS (in), 90 GND (power), 99 I2/CLK2 (in), 100 VCC (power), 101 GND (power), 102 I3/CLK3 (in), 111 GND (power), 120 TDO (out), 121 GND (power), 122 VCC (power), 131 GND (power), 132 VCC (power), 139 VCC (power), 140 GND (power), 141 GND (power), 142 VCC (power), 149 VCC (power), 150 GND (power), 159 VCC (power), 160 GND (power)

## M5LV-384/120-20HI
designator U?
High-Density and High-I/O Complex PLD
footprint MQFP160_N (QFP, 160-Leads, Body 27.7 x 27.7mm, Pitch 0.65mm, IPC Medium Density)
footprint MQFP160_L (QFP, 160-Leads, Body 27.7 x 27.7mm, Pitch 0.65mm, IPC High Density)
footprint MQFP160_M (QFP, 160-Leads, Body 27.7 x 27.7mm, Pitch 0.65mm, IPC Low Density)
3D model M5LV-MQFP160 (160-Pin Quad Flat Pack 0.65 mm Pitch)
part A pins: 2 I/O0 (0A2) (io), 3 I/O1 (0A3) (io), 4 I/O2 (0A4) (io), 5 I/O3 (0A7) (io), 6 I/O4 (0A8) (io), 7 I/O5 (0A11) (io), 8 I/O6 (0A12) (io), 9 I/O7 (0A13) (io), 11 I/O8 (0D13) (io), 12 I/O9 (0D12) (io), 13 I/O10 (0D11) (io), 14 I/O11 (0D8) (io), 15 I/O12 (0D7) (io), 16 I/O13 (0D4) (io), 17 I/O14 (0D3) (io), 18 I/O15 (0D2) (io), 23 I/O16 (1D2) (io), 24 I/O17 (1D3) (io), 25 I/O18 (1D4) (io), 26 I/O19 (1D7) (io), 27 I/O20 (1D8) (io), 28 I/O21 (1D11) (io), 29 I/O22 (1D12) (io), 30 I/O23 (1D13) (io), 32 I/O24 (1A13) (io), 33 I/O25 (1A12) (io), 34 I/O26 (1A11) (io), 35 I/O27 (1A8) (io), 36 I/O28 (1A7) (io), 37 I/O29 (1A4) (io), 38 I/O30 (1A3) (io), 39 I/O31 (1A2) (io), 43 I/O32 (1B2) (io), 44 I/O33 (1B3) (io), 45 I/O34 (1B4) (io), 46 I/O35 (1B7) (io), 47 I/O36 (1B8) (io), 48 I/O37 (1B11) (io), 49 I/O38 (1B12) (io), 50 I/O39 (1B13) (io), 53 I/O40 (2A12) (io), 54 I/O41 (2A11) (io), 55 I/O42 (2A8) (io), 56 I/O43 (2A7) (io), 57 I/O44 (2A4) (io), 58 I/O45 (2A3) (io), 63 I/O46 (2B3) (io), 64 I/O47 (2B4) (io), 65 I/O48 (2B7) (io), 66 I/O49 (2B8) (io), 67 I/O50 (2B11) (io), 68 I/O51 (2B12) (io), 71 I/O52 (3B13) (io), 72 I/O53 (3B12) (io), 73 I/O54 (3B11) (io), 74 I/O55 (3B8) (io), 75 I/O56 (3B7) (io), 76 I/O57 (3B4) (io), 77 I/O58 (3B3) (io), 78 I/O59 (3B2) (io), 82 I/O60 (3A2) (io), 83 I/O61 (3A3) (io), 84 I/O62 (3A4) (io), 85 I/O63 (3A7) (io), 86 I/O64 (3A8) (io), 87 I/O65 (3A11) (io), 88 I/O66 (3A12) (io), 89 I/O67 (3A13) (io), 91 I/O68 (3D13) (io), 92 I/O69 (3D12) (io), 93 I/O70 (3D11) (io), 94 I/O71 (3D8) (io), 95 I/O72 (3D7) (io), 96 I/O73 (3D4) (io), 97 I/O74 (3D3) (io), 98 I/O75 (3D2) (io), 103 I/O76 (4D2) (io), 104 I/O77 (4D3) (io), 105 I/O78 (4D4) (io), 106 I/O79 (4D7) (io), 107 I/O80 (4D8) (io), 108 I/O81 (4D11) (io), 109 I/O82 (4D12) (io), 110 I/O83 (4D13) (io), 112 I/O84 (4A13) (io), 113 I/O85 (4A12) (io), 114 I/O86 (4A11) (io), 115 I/O87 (4A8) (io), 116 I/O88 (4A7) (io), 117 I/O89 (4A4) (io), 118 I/O90 (4A3) (io), 119 I/O91 (4A2) (io), 123 I/O92 (4B2) (io), 124 I/O93 (4B3) (io), 125 I/O94 (4B4) (io), 126 I/O95 (4B7) (io), 127 I/O96 (4B8) (io), 128 I/O97 (4B11) (io), 129 I/O98 (4B12) (io), 130 I/O99 (4B13) (io), 133 I/O100 (5B12) (io), 134 I/O101 (5B11) (io), 135 I/O102 (5B8) (io), 136 I/O103 (5B7) (io), 137 I/O104 (5B4) (io), 138 I/O105 (5B3) (io), 143 I/O106 (5A3) (io), 144 I/O107 (5A4) (io), 145 I/O108 (5A7) (io), 146 I/O109 (5A8) (io), 147 I/O110 (5A11) (io), 148 I/O111 (5A12) (io), 151 I/O112 (0B13) (io), 152 I/O113 (0B12) (io), 153 I/O114 (0B11) (io), 154 I/O115 (0B8) (io), 155 I/O116 (0B7) (io), 156 I/O117 (0B4) (io), 157 I/O118 (0B3) (io), 158 I/O119 (0B2) (io)
part B pins: 1 TDI (in), 10 GND (power), 19 I0/CLK0 (in), 20 VCC (power), 21 GND (power), 22 I1/CLK1 (in), 31 GND (power), 40 TCK (in), 41 GND (power), 42 VCC (power), 51 GND (power), 52 VCC (power), 59 VCC (power), 60 GND (power), 61 GND (power), 62 VCC (power), 69 VCC (power), 70 GND (power), 79 VCC (power), 80 GND (power), 81 TMS (in), 90 GND (power), 99 I2/CLK2 (in), 100 VCC (power), 101 GND (power), 102 I3/CLK3 (in), 111 GND (power), 120 TDO (out), 121 GND (power), 122 VCC (power), 131 GND (power), 132 VCC (power), 139 VCC (power), 140 GND (power), 141 GND (power), 142 VCC (power), 149 VCC (power), 150 GND (power), 159 VCC (power), 160 GND (power)

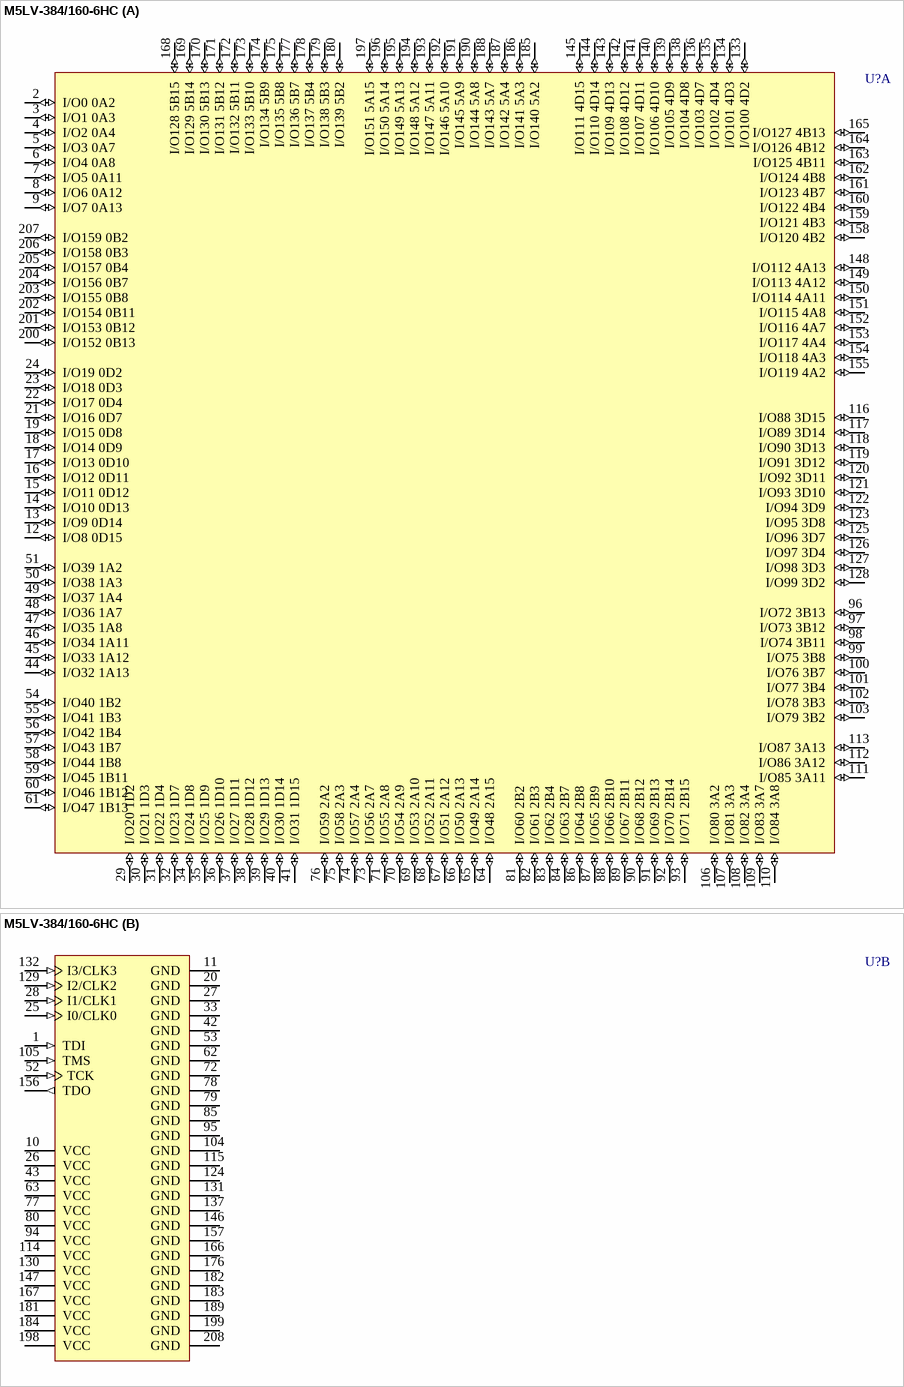
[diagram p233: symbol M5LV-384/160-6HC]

## M5LV-384/160-6HC
designator U?
High-Density and High-I/O Complex PLD
footprint MQFP208_N (Shrink QFP, 208-Leads, Body 27.7x27.7mm, Pitch 0.5mm, IPC Medium Density)
footprint MQFP208_L (Shrink QFP, 208-Leads, Body 27.7x27.7mm, Pitch 0.5mm, IPC High Density)
footprint MQFP208_M (Shrink QFP, 208-Leads, Body 27.7x27.7mm, Pitch 0.5mm, IPC Low Density)
3D model M5LV-MQFP208 (208-Pin Shrink Quad Flat Pack 0.5 mm Pitch)
part A pins: 2 I/O0 0A2 (io), 3 I/O1 0A3 (io), 4 I/O2 0A4 (io), 5 I/O3 0A7 (io), 6 I/O4 0A8 (io), 7 I/O5 0A11 (io), 8 I/O6 0A12 (io), 9 I/O7 0A13 (io), 12 I/O8 0D15 (io), 13 I/O9 0D14 (io), 14 I/O10 0D13 (io), 15 I/O11 0D12 (io), 16 I/O12 0D11 (io), 17 I/O13 0D10 (io), 18 I/O14 0D9 (io), 19 I/O15 0D8 (io), 21 I/O16 0D7 (io), 22 I/O17 0D4 (io), 23 I/O18 0D3 (io), 24 I/O19 0D2 (io), 29 I/O20 1D2 (io), 30 I/O21 1D3 (io), 31 I/O22 1D4 (io), 32 I/O23 1D7 (io), 34 I/O24 1D8 (io), 35 I/O25 1D9 (io), 36 I/O26 1D10 (io), 37 I/O27 1D11 (io), 38 I/O28 1D12 (io), 39 I/O29 1D13 (io), 40 I/O30 1D14 (io), 41 I/O31 1D15 (io), 44 I/O32 1A13 (io), 45 I/O33 1A12 (io), 46 I/O34 1A11 (io), 47 I/O35 1A8 (io), 48 I/O36 1A7 (io), 49 I/O37 1A4 (io), 50 I/O38 1A3 (io), 51 I/O39 1A2 (io), 54 I/O40 1B2 (io), 55 I/O41 1B3 (io), 56 I/O42 1B4 (io), 57 I/O43 1B7 (io), 58 I/O44 1B8 (io), 59 I/O45 1B11 (io), 60 I/O46 1B12 (io), 61 I/O47 1B13 (io), 64 I/O48 2A15 (io), 65 I/O49 2A14 (io), 66 I/O50 2A13 (io), 67 I/O51 2A12 (io), 68 I/O52 2A11 (io), 69 I/O53 2A10 (io), 70 I/O54 2A9 (io), 71 I/O55 2A8 (io), 73 I/O56 2A7 (io), 74 I/O57 2A4 (io), 75 I/O58 2A3 (io), 76 I/O59 2A2 (io), 81 I/O60 2B2 (io), 82 I/O61 2B3 (io), 83 I/O62 2B4 (io), 84 I/O63 2B7 (io), 86 I/O64 2B8 (io), 87 I/O65 2B9 (io), 88 I/O66 2B10 (io), 89 I/O67 2B11 (io), 90 I/O68 2B12 (io), 91 I/O69 2B13 (io), 92 I/O70 2B14 (io), 93 I/O71 2B15 (io), 96 I/O72 3B13 (io), 97 I/O73 3B12 (io), 98 I/O74 3B11 (io), 99 I/O75 3B8 (io), 100 I/O76 3B7 (io), 101 I/O77 3B4 (io), 102 I/O78 3B3 (io), 103 I/O79 3B2 (io), 106 I/O80 3A2 (io), 107 I/O81 3A3 (io), 108 I/O82 3A4 (io), 109 I/O83 3A7 (io), 110 I/O84 3A8 (io), 111 I/O85 3A11 (io), 112 I/O86 3A12 (io), 113 I/O87 3A13 (io), 116 I/O88 3D15 (io), 117 I/O89 3D14 (io), 118 I/O90 3D13 (io), 119 I/O91 3D12 (io), 120 I/O92 3D11 (io), 121 I/O93 3D10 (io), 122 I/O94 3D9 (io), 123 I/O95 3D8 (io), 125 I/O96 3D7 (io), 126 I/O97 3D4 (io), 127 I/O98 3D3 (io), 128 I/O99 3D2 (io), 133 I/O100 4D2 (io), 134 I/O101 4D3 (io), 135 I/O102 4D4 (io), 136 I/O103 4D7 (io), 138 I/O104 4D8 (io), 139 I/O105 4D9 (io), 140 I/O106 4D10 (io), 141 I/O107 4D11 (io), 142 I/O108 4D12 (io), 143 I/O109 4D13 (io), 144 I/O110 4D14 (io), 145 I/O111 4D15 (io), 148 I/O112 4A13 (io), 149 I/O113 4A12 (io), 150 I/O114 4A11 (io), 151 I/O115 4A8 (io), 152 I/O116 4A7 (io), 153 I/O117 4A4 (io), 154 I/O118 4A3 (io), 155 I/O119 4A2 (io), 158 I/O120 4B2 (io), 159 I/O121 4B3 (io), 160 I/O122 4B4 (io), 161 I/O123 4B7 (io), 162 I/O124 4B8 (io), 163 I/O125 4B11 (io), 164 I/O126 4B12 (io), 165 I/O127 4B13 (io), 168 I/O128 5B15 (io), 169 I/O129 5B14 (io), 170 I/O130 5B13 (io), 171 I/O131 5B12 (io), 172 I/O132 5B11 (io), 173 I/O133 5B10 (io), 174 I/O134 5B9 (io), 175 I/O135 5B8 (io), 177 I/O136 5B7 (io), 178 I/O137 5B4 (io), 179 I/O138 5B3 (io), 180 I/O139 5B2 (io), 185 I/O140 5A2 (io), 186 I/O141 5A3 (io), 187 I/O142 5A4 (io), 188 I/O143 5A7 (io), 190 I/O144 5A8 (io), 191 I/O145 5A9 (io), 192 I/O146 5A10 (io), 193 I/O147 5A11 (io), 194 I/O148 5A12 (io), 195 I/O149 5A13 (io), 196 I/O150 5A14 (io), 197 I/O151 5A15 (io), 200 I/O152 0B13 (io), 201 I/O153 0B12 (io), 202 I/O154 0B11 (io), 203 I/O155 0B8 (io), 204 I/O156 0B7 (io), 205 I/O157 0B4 (io), 206 I/O158 0B3 (io), 207 I/O159 0B2 (io)
part B pins: 1 TDI (in), 10 VCC (power), 11 GND (power), 20 GND (power), 25 I0/CLK0 (in), 26 VCC (power), 27 GND (power), 28 I1/CLK1 (in), 33 GND (power), 42 GND (power), 43 VCC (power), 52 TCK (in), 53 GND (power), 62 GND (power), 63 VCC (power), 72 GND (power), 77 VCC (power), 78 GND (power), 79 GND (power), 80 VCC (power), 85 GND (power), 94 VCC (power), 95 GND (power), 104 GND (power), 105 TMS (in), 114 VCC (power), 115 GND (power), 124 GND (power), 129 I2/CLK2 (in), 130 VCC (power), 131 GND (power), 132 I3/CLK3 (in), 137 GND (power), 146 GND (power), 147 VCC (power), 156 TDO (out), 157 GND (power), 166 GND (power), 167 VCC (power), 176 GND (power), 181 VCC (power), 182 GND (power), 183 GND (power), 184 VCC (power), 189 GND (power), 198 VCC (power), 199 GND (power), 208 GND (power)

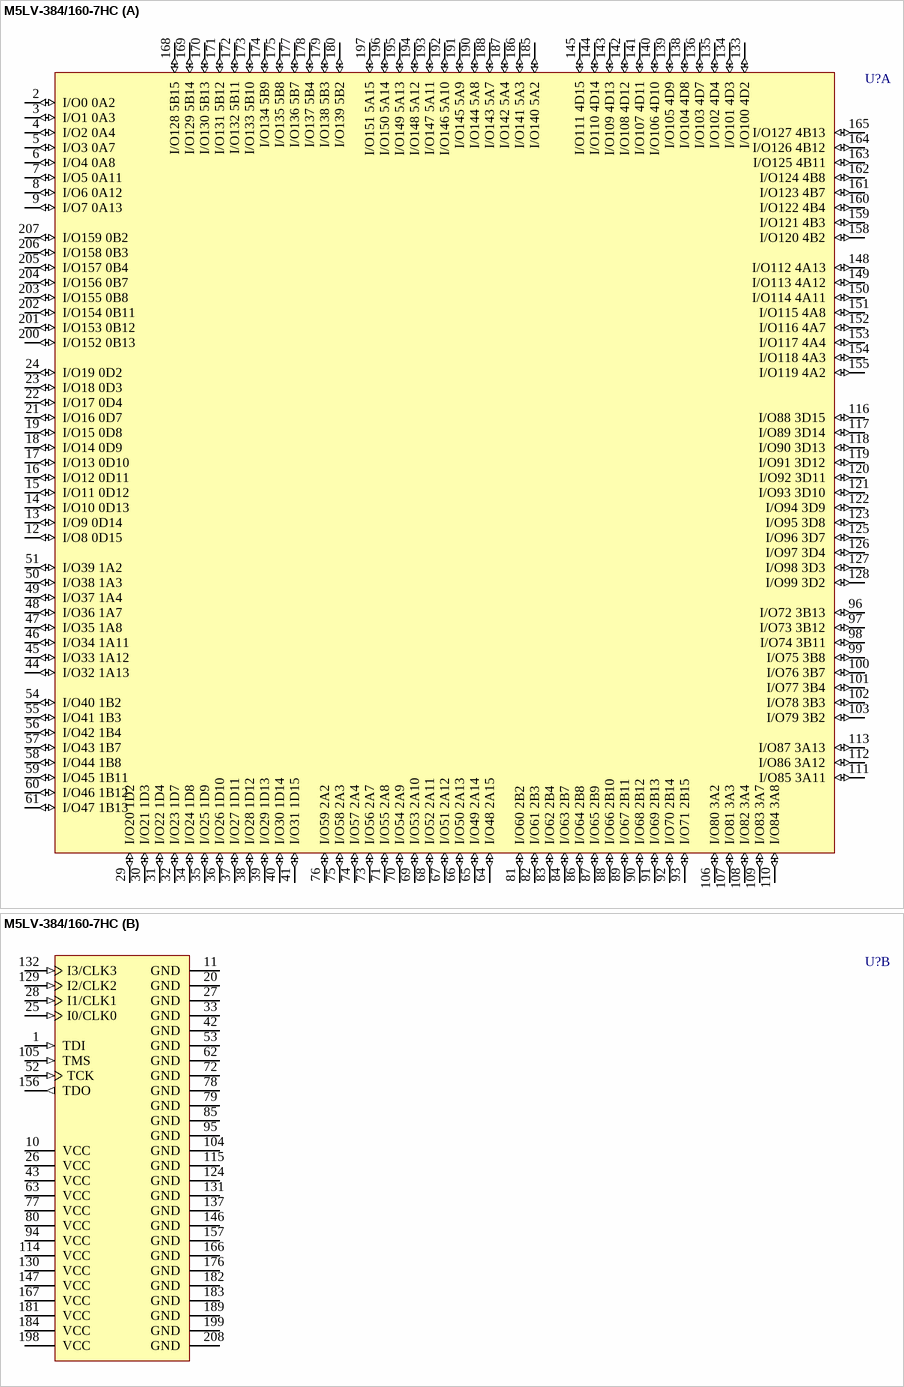
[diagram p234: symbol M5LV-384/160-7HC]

## M5LV-384/160-7HC
designator U?
High-Density and High-I/O Complex PLD
footprint MQFP208_N (Shrink QFP, 208-Leads, Body 27.7x27.7mm, Pitch 0.5mm, IPC Medium Density)
footprint MQFP208_L (Shrink QFP, 208-Leads, Body 27.7x27.7mm, Pitch 0.5mm, IPC High Density)
footprint MQFP208_M (Shrink QFP, 208-Leads, Body 27.7x27.7mm, Pitch 0.5mm, IPC Low Density)
3D model M5LV-MQFP208 (208-Pin Shrink Quad Flat Pack 0.5 mm Pitch)
part A pins: 2 I/O0 0A2 (io), 3 I/O1 0A3 (io), 4 I/O2 0A4 (io), 5 I/O3 0A7 (io), 6 I/O4 0A8 (io), 7 I/O5 0A11 (io), 8 I/O6 0A12 (io), 9 I/O7 0A13 (io), 12 I/O8 0D15 (io), 13 I/O9 0D14 (io), 14 I/O10 0D13 (io), 15 I/O11 0D12 (io), 16 I/O12 0D11 (io), 17 I/O13 0D10 (io), 18 I/O14 0D9 (io), 19 I/O15 0D8 (io), 21 I/O16 0D7 (io), 22 I/O17 0D4 (io), 23 I/O18 0D3 (io), 24 I/O19 0D2 (io), 29 I/O20 1D2 (io), 30 I/O21 1D3 (io), 31 I/O22 1D4 (io), 32 I/O23 1D7 (io), 34 I/O24 1D8 (io), 35 I/O25 1D9 (io), 36 I/O26 1D10 (io), 37 I/O27 1D11 (io), 38 I/O28 1D12 (io), 39 I/O29 1D13 (io), 40 I/O30 1D14 (io), 41 I/O31 1D15 (io), 44 I/O32 1A13 (io), 45 I/O33 1A12 (io), 46 I/O34 1A11 (io), 47 I/O35 1A8 (io), 48 I/O36 1A7 (io), 49 I/O37 1A4 (io), 50 I/O38 1A3 (io), 51 I/O39 1A2 (io), 54 I/O40 1B2 (io), 55 I/O41 1B3 (io), 56 I/O42 1B4 (io), 57 I/O43 1B7 (io), 58 I/O44 1B8 (io), 59 I/O45 1B11 (io), 60 I/O46 1B12 (io), 61 I/O47 1B13 (io), 64 I/O48 2A15 (io), 65 I/O49 2A14 (io), 66 I/O50 2A13 (io), 67 I/O51 2A12 (io), 68 I/O52 2A11 (io), 69 I/O53 2A10 (io), 70 I/O54 2A9 (io), 71 I/O55 2A8 (io), 73 I/O56 2A7 (io), 74 I/O57 2A4 (io), 75 I/O58 2A3 (io), 76 I/O59 2A2 (io), 81 I/O60 2B2 (io), 82 I/O61 2B3 (io), 83 I/O62 2B4 (io), 84 I/O63 2B7 (io), 86 I/O64 2B8 (io), 87 I/O65 2B9 (io), 88 I/O66 2B10 (io), 89 I/O67 2B11 (io), 90 I/O68 2B12 (io), 91 I/O69 2B13 (io), 92 I/O70 2B14 (io), 93 I/O71 2B15 (io), 96 I/O72 3B13 (io), 97 I/O73 3B12 (io), 98 I/O74 3B11 (io), 99 I/O75 3B8 (io), 100 I/O76 3B7 (io), 101 I/O77 3B4 (io), 102 I/O78 3B3 (io), 103 I/O79 3B2 (io), 106 I/O80 3A2 (io), 107 I/O81 3A3 (io), 108 I/O82 3A4 (io), 109 I/O83 3A7 (io), 110 I/O84 3A8 (io), 111 I/O85 3A11 (io), 112 I/O86 3A12 (io), 113 I/O87 3A13 (io), 116 I/O88 3D15 (io), 117 I/O89 3D14 (io), 118 I/O90 3D13 (io), 119 I/O91 3D12 (io), 120 I/O92 3D11 (io), 121 I/O93 3D10 (io), 122 I/O94 3D9 (io), 123 I/O95 3D8 (io), 125 I/O96 3D7 (io), 126 I/O97 3D4 (io), 127 I/O98 3D3 (io), 128 I/O99 3D2 (io), 133 I/O100 4D2 (io), 134 I/O101 4D3 (io), 135 I/O102 4D4 (io), 136 I/O103 4D7 (io), 138 I/O104 4D8 (io), 139 I/O105 4D9 (io), 140 I/O106 4D10 (io), 141 I/O107 4D11 (io), 142 I/O108 4D12 (io), 143 I/O109 4D13 (io), 144 I/O110 4D14 (io), 145 I/O111 4D15 (io), 148 I/O112 4A13 (io), 149 I/O113 4A12 (io), 150 I/O114 4A11 (io), 151 I/O115 4A8 (io), 152 I/O116 4A7 (io), 153 I/O117 4A4 (io), 154 I/O118 4A3 (io), 155 I/O119 4A2 (io), 158 I/O120 4B2 (io), 159 I/O121 4B3 (io), 160 I/O122 4B4 (io), 161 I/O123 4B7 (io), 162 I/O124 4B8 (io), 163 I/O125 4B11 (io), 164 I/O126 4B12 (io), 165 I/O127 4B13 (io), 168 I/O128 5B15 (io), 169 I/O129 5B14 (io), 170 I/O130 5B13 (io), 171 I/O131 5B12 (io), 172 I/O132 5B11 (io), 173 I/O133 5B10 (io), 174 I/O134 5B9 (io), 175 I/O135 5B8 (io), 177 I/O136 5B7 (io), 178 I/O137 5B4 (io), 179 I/O138 5B3 (io), 180 I/O139 5B2 (io), 185 I/O140 5A2 (io), 186 I/O141 5A3 (io), 187 I/O142 5A4 (io), 188 I/O143 5A7 (io), 190 I/O144 5A8 (io), 191 I/O145 5A9 (io), 192 I/O146 5A10 (io), 193 I/O147 5A11 (io), 194 I/O148 5A12 (io), 195 I/O149 5A13 (io), 196 I/O150 5A14 (io), 197 I/O151 5A15 (io), 200 I/O152 0B13 (io), 201 I/O153 0B12 (io), 202 I/O154 0B11 (io), 203 I/O155 0B8 (io), 204 I/O156 0B7 (io), 205 I/O157 0B4 (io), 206 I/O158 0B3 (io), 207 I/O159 0B2 (io)
part B pins: 1 TDI (in), 10 VCC (power), 11 GND (power), 20 GND (power), 25 I0/CLK0 (in), 26 VCC (power), 27 GND (power), 28 I1/CLK1 (in), 33 GND (power), 42 GND (power), 43 VCC (power), 52 TCK (in), 53 GND (power), 62 GND (power), 63 VCC (power), 72 GND (power), 77 VCC (power), 78 GND (power), 79 GND (power), 80 VCC (power), 85 GND (power), 94 VCC (power), 95 GND (power), 104 GND (power), 105 TMS (in), 114 VCC (power), 115 GND (power), 124 GND (power), 129 I2/CLK2 (in), 130 VCC (power), 131 GND (power), 132 I3/CLK3 (in), 137 GND (power), 146 GND (power), 147 VCC (power), 156 TDO (out), 157 GND (power), 166 GND (power), 167 VCC (power), 176 GND (power), 181 VCC (power), 182 GND (power), 183 GND (power), 184 VCC (power), 189 GND (power), 198 VCC (power), 199 GND (power), 208 GND (power)

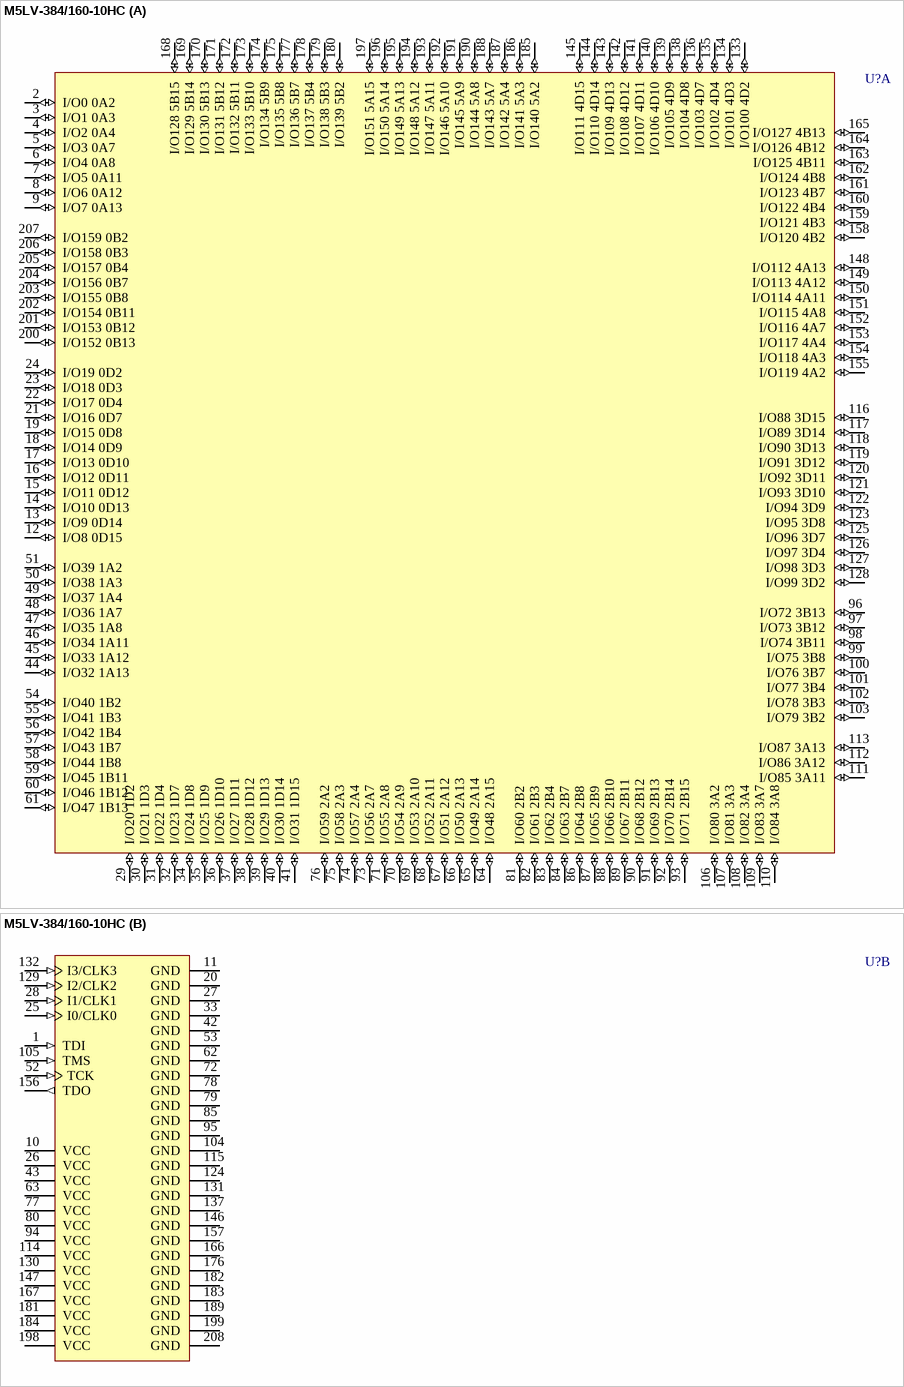
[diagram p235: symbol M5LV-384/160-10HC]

## M5LV-384/160-10HC
designator U?
High-Density and High-I/O Complex PLD
footprint MQFP208_N (Shrink QFP, 208-Leads, Body 27.7x27.7mm, Pitch 0.5mm, IPC Medium Density)
footprint MQFP208_L (Shrink QFP, 208-Leads, Body 27.7x27.7mm, Pitch 0.5mm, IPC High Density)
footprint MQFP208_M (Shrink QFP, 208-Leads, Body 27.7x27.7mm, Pitch 0.5mm, IPC Low Density)
3D model M5LV-MQFP208 (208-Pin Shrink Quad Flat Pack 0.5 mm Pitch)
part A pins: 2 I/O0 0A2 (io), 3 I/O1 0A3 (io), 4 I/O2 0A4 (io), 5 I/O3 0A7 (io), 6 I/O4 0A8 (io), 7 I/O5 0A11 (io), 8 I/O6 0A12 (io), 9 I/O7 0A13 (io), 12 I/O8 0D15 (io), 13 I/O9 0D14 (io), 14 I/O10 0D13 (io), 15 I/O11 0D12 (io), 16 I/O12 0D11 (io), 17 I/O13 0D10 (io), 18 I/O14 0D9 (io), 19 I/O15 0D8 (io), 21 I/O16 0D7 (io), 22 I/O17 0D4 (io), 23 I/O18 0D3 (io), 24 I/O19 0D2 (io), 29 I/O20 1D2 (io), 30 I/O21 1D3 (io), 31 I/O22 1D4 (io), 32 I/O23 1D7 (io), 34 I/O24 1D8 (io), 35 I/O25 1D9 (io), 36 I/O26 1D10 (io), 37 I/O27 1D11 (io), 38 I/O28 1D12 (io), 39 I/O29 1D13 (io), 40 I/O30 1D14 (io), 41 I/O31 1D15 (io), 44 I/O32 1A13 (io), 45 I/O33 1A12 (io), 46 I/O34 1A11 (io), 47 I/O35 1A8 (io), 48 I/O36 1A7 (io), 49 I/O37 1A4 (io), 50 I/O38 1A3 (io), 51 I/O39 1A2 (io), 54 I/O40 1B2 (io), 55 I/O41 1B3 (io), 56 I/O42 1B4 (io), 57 I/O43 1B7 (io), 58 I/O44 1B8 (io), 59 I/O45 1B11 (io), 60 I/O46 1B12 (io), 61 I/O47 1B13 (io), 64 I/O48 2A15 (io), 65 I/O49 2A14 (io), 66 I/O50 2A13 (io), 67 I/O51 2A12 (io), 68 I/O52 2A11 (io), 69 I/O53 2A10 (io), 70 I/O54 2A9 (io), 71 I/O55 2A8 (io), 73 I/O56 2A7 (io), 74 I/O57 2A4 (io), 75 I/O58 2A3 (io), 76 I/O59 2A2 (io), 81 I/O60 2B2 (io), 82 I/O61 2B3 (io), 83 I/O62 2B4 (io), 84 I/O63 2B7 (io), 86 I/O64 2B8 (io), 87 I/O65 2B9 (io), 88 I/O66 2B10 (io), 89 I/O67 2B11 (io), 90 I/O68 2B12 (io), 91 I/O69 2B13 (io), 92 I/O70 2B14 (io), 93 I/O71 2B15 (io), 96 I/O72 3B13 (io), 97 I/O73 3B12 (io), 98 I/O74 3B11 (io), 99 I/O75 3B8 (io), 100 I/O76 3B7 (io), 101 I/O77 3B4 (io), 102 I/O78 3B3 (io), 103 I/O79 3B2 (io), 106 I/O80 3A2 (io), 107 I/O81 3A3 (io), 108 I/O82 3A4 (io), 109 I/O83 3A7 (io), 110 I/O84 3A8 (io), 111 I/O85 3A11 (io), 112 I/O86 3A12 (io), 113 I/O87 3A13 (io), 116 I/O88 3D15 (io), 117 I/O89 3D14 (io), 118 I/O90 3D13 (io), 119 I/O91 3D12 (io), 120 I/O92 3D11 (io), 121 I/O93 3D10 (io), 122 I/O94 3D9 (io), 123 I/O95 3D8 (io), 125 I/O96 3D7 (io), 126 I/O97 3D4 (io), 127 I/O98 3D3 (io), 128 I/O99 3D2 (io), 133 I/O100 4D2 (io), 134 I/O101 4D3 (io), 135 I/O102 4D4 (io), 136 I/O103 4D7 (io), 138 I/O104 4D8 (io), 139 I/O105 4D9 (io), 140 I/O106 4D10 (io), 141 I/O107 4D11 (io), 142 I/O108 4D12 (io), 143 I/O109 4D13 (io), 144 I/O110 4D14 (io), 145 I/O111 4D15 (io), 148 I/O112 4A13 (io), 149 I/O113 4A12 (io), 150 I/O114 4A11 (io), 151 I/O115 4A8 (io), 152 I/O116 4A7 (io), 153 I/O117 4A4 (io), 154 I/O118 4A3 (io), 155 I/O119 4A2 (io), 158 I/O120 4B2 (io), 159 I/O121 4B3 (io), 160 I/O122 4B4 (io), 161 I/O123 4B7 (io), 162 I/O124 4B8 (io), 163 I/O125 4B11 (io), 164 I/O126 4B12 (io), 165 I/O127 4B13 (io), 168 I/O128 5B15 (io), 169 I/O129 5B14 (io), 170 I/O130 5B13 (io), 171 I/O131 5B12 (io), 172 I/O132 5B11 (io), 173 I/O133 5B10 (io), 174 I/O134 5B9 (io), 175 I/O135 5B8 (io), 177 I/O136 5B7 (io), 178 I/O137 5B4 (io), 179 I/O138 5B3 (io), 180 I/O139 5B2 (io), 185 I/O140 5A2 (io), 186 I/O141 5A3 (io), 187 I/O142 5A4 (io), 188 I/O143 5A7 (io), 190 I/O144 5A8 (io), 191 I/O145 5A9 (io), 192 I/O146 5A10 (io), 193 I/O147 5A11 (io), 194 I/O148 5A12 (io), 195 I/O149 5A13 (io), 196 I/O150 5A14 (io), 197 I/O151 5A15 (io), 200 I/O152 0B13 (io), 201 I/O153 0B12 (io), 202 I/O154 0B11 (io), 203 I/O155 0B8 (io), 204 I/O156 0B7 (io), 205 I/O157 0B4 (io), 206 I/O158 0B3 (io), 207 I/O159 0B2 (io)
part B pins: 1 TDI (in), 10 VCC (power), 11 GND (power), 20 GND (power), 25 I0/CLK0 (in), 26 VCC (power), 27 GND (power), 28 I1/CLK1 (in), 33 GND (power), 42 GND (power), 43 VCC (power), 52 TCK (in), 53 GND (power), 62 GND (power), 63 VCC (power), 72 GND (power), 77 VCC (power), 78 GND (power), 79 GND (power), 80 VCC (power), 85 GND (power), 94 VCC (power), 95 GND (power), 104 GND (power), 105 TMS (in), 114 VCC (power), 115 GND (power), 124 GND (power), 129 I2/CLK2 (in), 130 VCC (power), 131 GND (power), 132 I3/CLK3 (in), 137 GND (power), 146 GND (power), 147 VCC (power), 156 TDO (out), 157 GND (power), 166 GND (power), 167 VCC (power), 176 GND (power), 181 VCC (power), 182 GND (power), 183 GND (power), 184 VCC (power), 189 GND (power), 198 VCC (power), 199 GND (power), 208 GND (power)

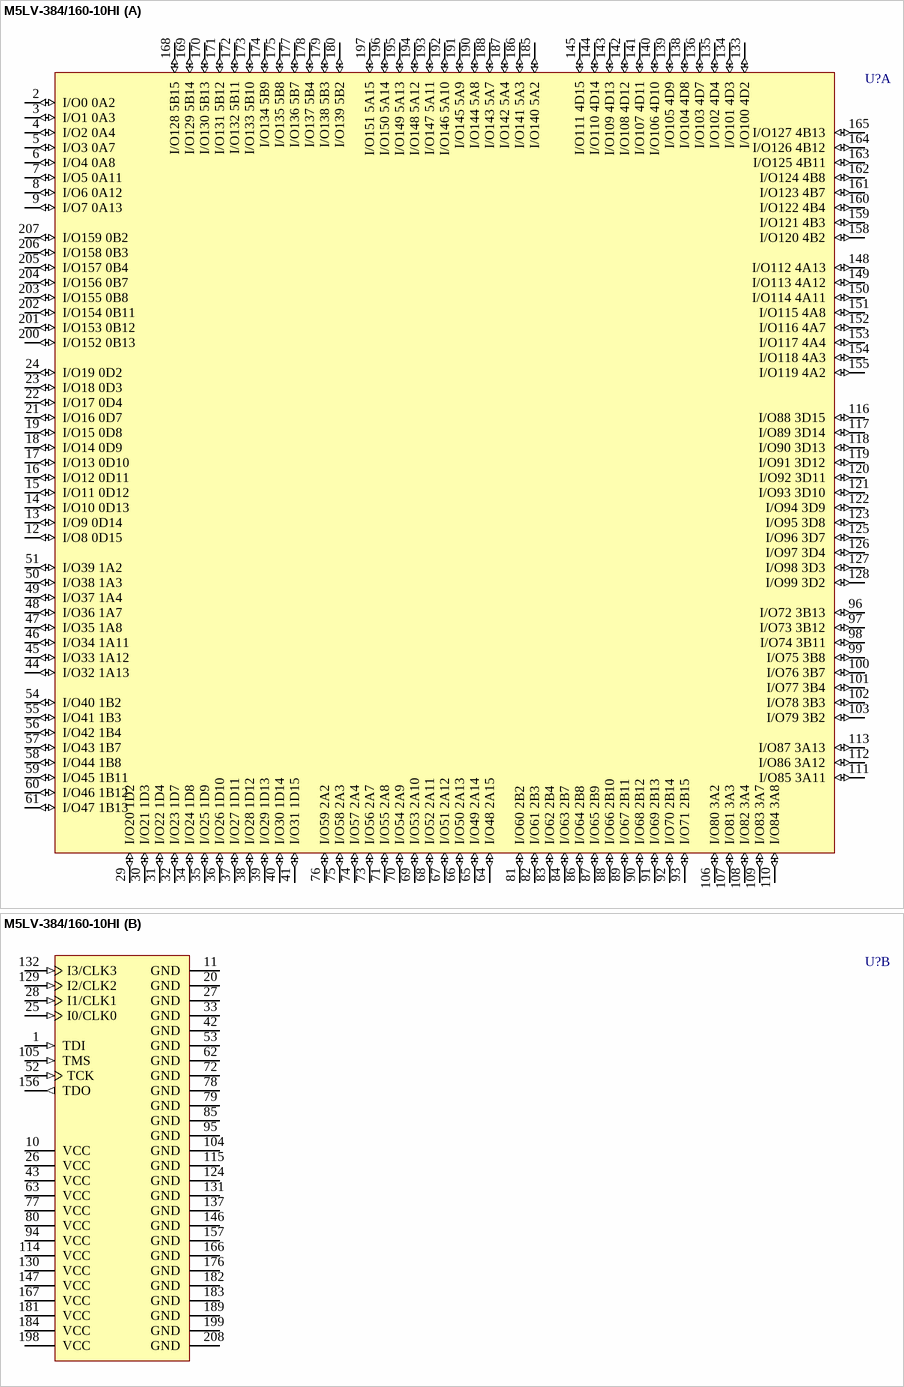
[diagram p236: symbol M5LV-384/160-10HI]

## M5LV-384/160-10HI
designator U?
High-Density and High-I/O Complex PLD
footprint MQFP208_N (Shrink QFP, 208-Leads, Body 27.7x27.7mm, Pitch 0.5mm, IPC Medium Density)
footprint MQFP208_L (Shrink QFP, 208-Leads, Body 27.7x27.7mm, Pitch 0.5mm, IPC High Density)
footprint MQFP208_M (Shrink QFP, 208-Leads, Body 27.7x27.7mm, Pitch 0.5mm, IPC Low Density)
3D model M5LV-MQFP208 (208-Pin Shrink Quad Flat Pack 0.5 mm Pitch)
part A pins: 2 I/O0 0A2 (io), 3 I/O1 0A3 (io), 4 I/O2 0A4 (io), 5 I/O3 0A7 (io), 6 I/O4 0A8 (io), 7 I/O5 0A11 (io), 8 I/O6 0A12 (io), 9 I/O7 0A13 (io), 12 I/O8 0D15 (io), 13 I/O9 0D14 (io), 14 I/O10 0D13 (io), 15 I/O11 0D12 (io), 16 I/O12 0D11 (io), 17 I/O13 0D10 (io), 18 I/O14 0D9 (io), 19 I/O15 0D8 (io), 21 I/O16 0D7 (io), 22 I/O17 0D4 (io), 23 I/O18 0D3 (io), 24 I/O19 0D2 (io), 29 I/O20 1D2 (io), 30 I/O21 1D3 (io), 31 I/O22 1D4 (io), 32 I/O23 1D7 (io), 34 I/O24 1D8 (io), 35 I/O25 1D9 (io), 36 I/O26 1D10 (io), 37 I/O27 1D11 (io), 38 I/O28 1D12 (io), 39 I/O29 1D13 (io), 40 I/O30 1D14 (io), 41 I/O31 1D15 (io), 44 I/O32 1A13 (io), 45 I/O33 1A12 (io), 46 I/O34 1A11 (io), 47 I/O35 1A8 (io), 48 I/O36 1A7 (io), 49 I/O37 1A4 (io), 50 I/O38 1A3 (io), 51 I/O39 1A2 (io), 54 I/O40 1B2 (io), 55 I/O41 1B3 (io), 56 I/O42 1B4 (io), 57 I/O43 1B7 (io), 58 I/O44 1B8 (io), 59 I/O45 1B11 (io), 60 I/O46 1B12 (io), 61 I/O47 1B13 (io), 64 I/O48 2A15 (io), 65 I/O49 2A14 (io), 66 I/O50 2A13 (io), 67 I/O51 2A12 (io), 68 I/O52 2A11 (io), 69 I/O53 2A10 (io), 70 I/O54 2A9 (io), 71 I/O55 2A8 (io), 73 I/O56 2A7 (io), 74 I/O57 2A4 (io), 75 I/O58 2A3 (io), 76 I/O59 2A2 (io), 81 I/O60 2B2 (io), 82 I/O61 2B3 (io), 83 I/O62 2B4 (io), 84 I/O63 2B7 (io), 86 I/O64 2B8 (io), 87 I/O65 2B9 (io), 88 I/O66 2B10 (io), 89 I/O67 2B11 (io), 90 I/O68 2B12 (io), 91 I/O69 2B13 (io), 92 I/O70 2B14 (io), 93 I/O71 2B15 (io), 96 I/O72 3B13 (io), 97 I/O73 3B12 (io), 98 I/O74 3B11 (io), 99 I/O75 3B8 (io), 100 I/O76 3B7 (io), 101 I/O77 3B4 (io), 102 I/O78 3B3 (io), 103 I/O79 3B2 (io), 106 I/O80 3A2 (io), 107 I/O81 3A3 (io), 108 I/O82 3A4 (io), 109 I/O83 3A7 (io), 110 I/O84 3A8 (io), 111 I/O85 3A11 (io), 112 I/O86 3A12 (io), 113 I/O87 3A13 (io), 116 I/O88 3D15 (io), 117 I/O89 3D14 (io), 118 I/O90 3D13 (io), 119 I/O91 3D12 (io), 120 I/O92 3D11 (io), 121 I/O93 3D10 (io), 122 I/O94 3D9 (io), 123 I/O95 3D8 (io), 125 I/O96 3D7 (io), 126 I/O97 3D4 (io), 127 I/O98 3D3 (io), 128 I/O99 3D2 (io), 133 I/O100 4D2 (io), 134 I/O101 4D3 (io), 135 I/O102 4D4 (io), 136 I/O103 4D7 (io), 138 I/O104 4D8 (io), 139 I/O105 4D9 (io), 140 I/O106 4D10 (io), 141 I/O107 4D11 (io), 142 I/O108 4D12 (io), 143 I/O109 4D13 (io), 144 I/O110 4D14 (io), 145 I/O111 4D15 (io), 148 I/O112 4A13 (io), 149 I/O113 4A12 (io), 150 I/O114 4A11 (io), 151 I/O115 4A8 (io), 152 I/O116 4A7 (io), 153 I/O117 4A4 (io), 154 I/O118 4A3 (io), 155 I/O119 4A2 (io), 158 I/O120 4B2 (io), 159 I/O121 4B3 (io), 160 I/O122 4B4 (io), 161 I/O123 4B7 (io), 162 I/O124 4B8 (io), 163 I/O125 4B11 (io), 164 I/O126 4B12 (io), 165 I/O127 4B13 (io), 168 I/O128 5B15 (io), 169 I/O129 5B14 (io), 170 I/O130 5B13 (io), 171 I/O131 5B12 (io), 172 I/O132 5B11 (io), 173 I/O133 5B10 (io), 174 I/O134 5B9 (io), 175 I/O135 5B8 (io), 177 I/O136 5B7 (io), 178 I/O137 5B4 (io), 179 I/O138 5B3 (io), 180 I/O139 5B2 (io), 185 I/O140 5A2 (io), 186 I/O141 5A3 (io), 187 I/O142 5A4 (io), 188 I/O143 5A7 (io), 190 I/O144 5A8 (io), 191 I/O145 5A9 (io), 192 I/O146 5A10 (io), 193 I/O147 5A11 (io), 194 I/O148 5A12 (io), 195 I/O149 5A13 (io), 196 I/O150 5A14 (io), 197 I/O151 5A15 (io), 200 I/O152 0B13 (io), 201 I/O153 0B12 (io), 202 I/O154 0B11 (io), 203 I/O155 0B8 (io), 204 I/O156 0B7 (io), 205 I/O157 0B4 (io), 206 I/O158 0B3 (io), 207 I/O159 0B2 (io)
part B pins: 1 TDI (in), 10 VCC (power), 11 GND (power), 20 GND (power), 25 I0/CLK0 (in), 26 VCC (power), 27 GND (power), 28 I1/CLK1 (in), 33 GND (power), 42 GND (power), 43 VCC (power), 52 TCK (in), 53 GND (power), 62 GND (power), 63 VCC (power), 72 GND (power), 77 VCC (power), 78 GND (power), 79 GND (power), 80 VCC (power), 85 GND (power), 94 VCC (power), 95 GND (power), 104 GND (power), 105 TMS (in), 114 VCC (power), 115 GND (power), 124 GND (power), 129 I2/CLK2 (in), 130 VCC (power), 131 GND (power), 132 I3/CLK3 (in), 137 GND (power), 146 GND (power), 147 VCC (power), 156 TDO (out), 157 GND (power), 166 GND (power), 167 VCC (power), 176 GND (power), 181 VCC (power), 182 GND (power), 183 GND (power), 184 VCC (power), 189 GND (power), 198 VCC (power), 199 GND (power), 208 GND (power)

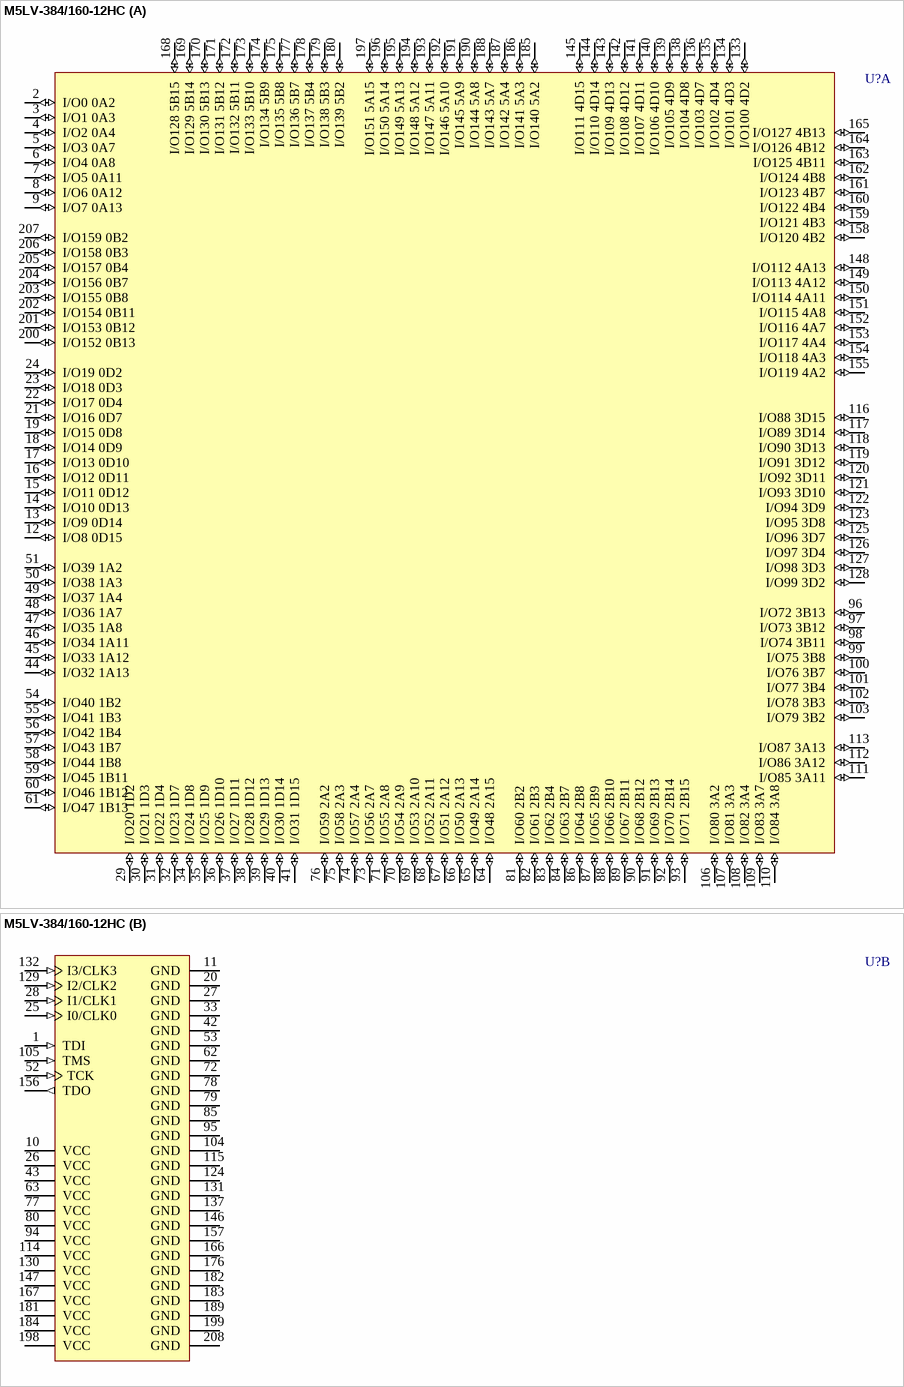
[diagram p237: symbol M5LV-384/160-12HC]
